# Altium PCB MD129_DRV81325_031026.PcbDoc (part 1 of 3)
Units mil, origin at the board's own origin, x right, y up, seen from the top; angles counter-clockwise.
Board outline 4300.91 x 4001.52 mil, 4 copper layers (Top Layer, GND, PWR, Bottom Layer), stack 92.668 mil thick; 211 components, 89 nets, 489 pads, 980 vias.
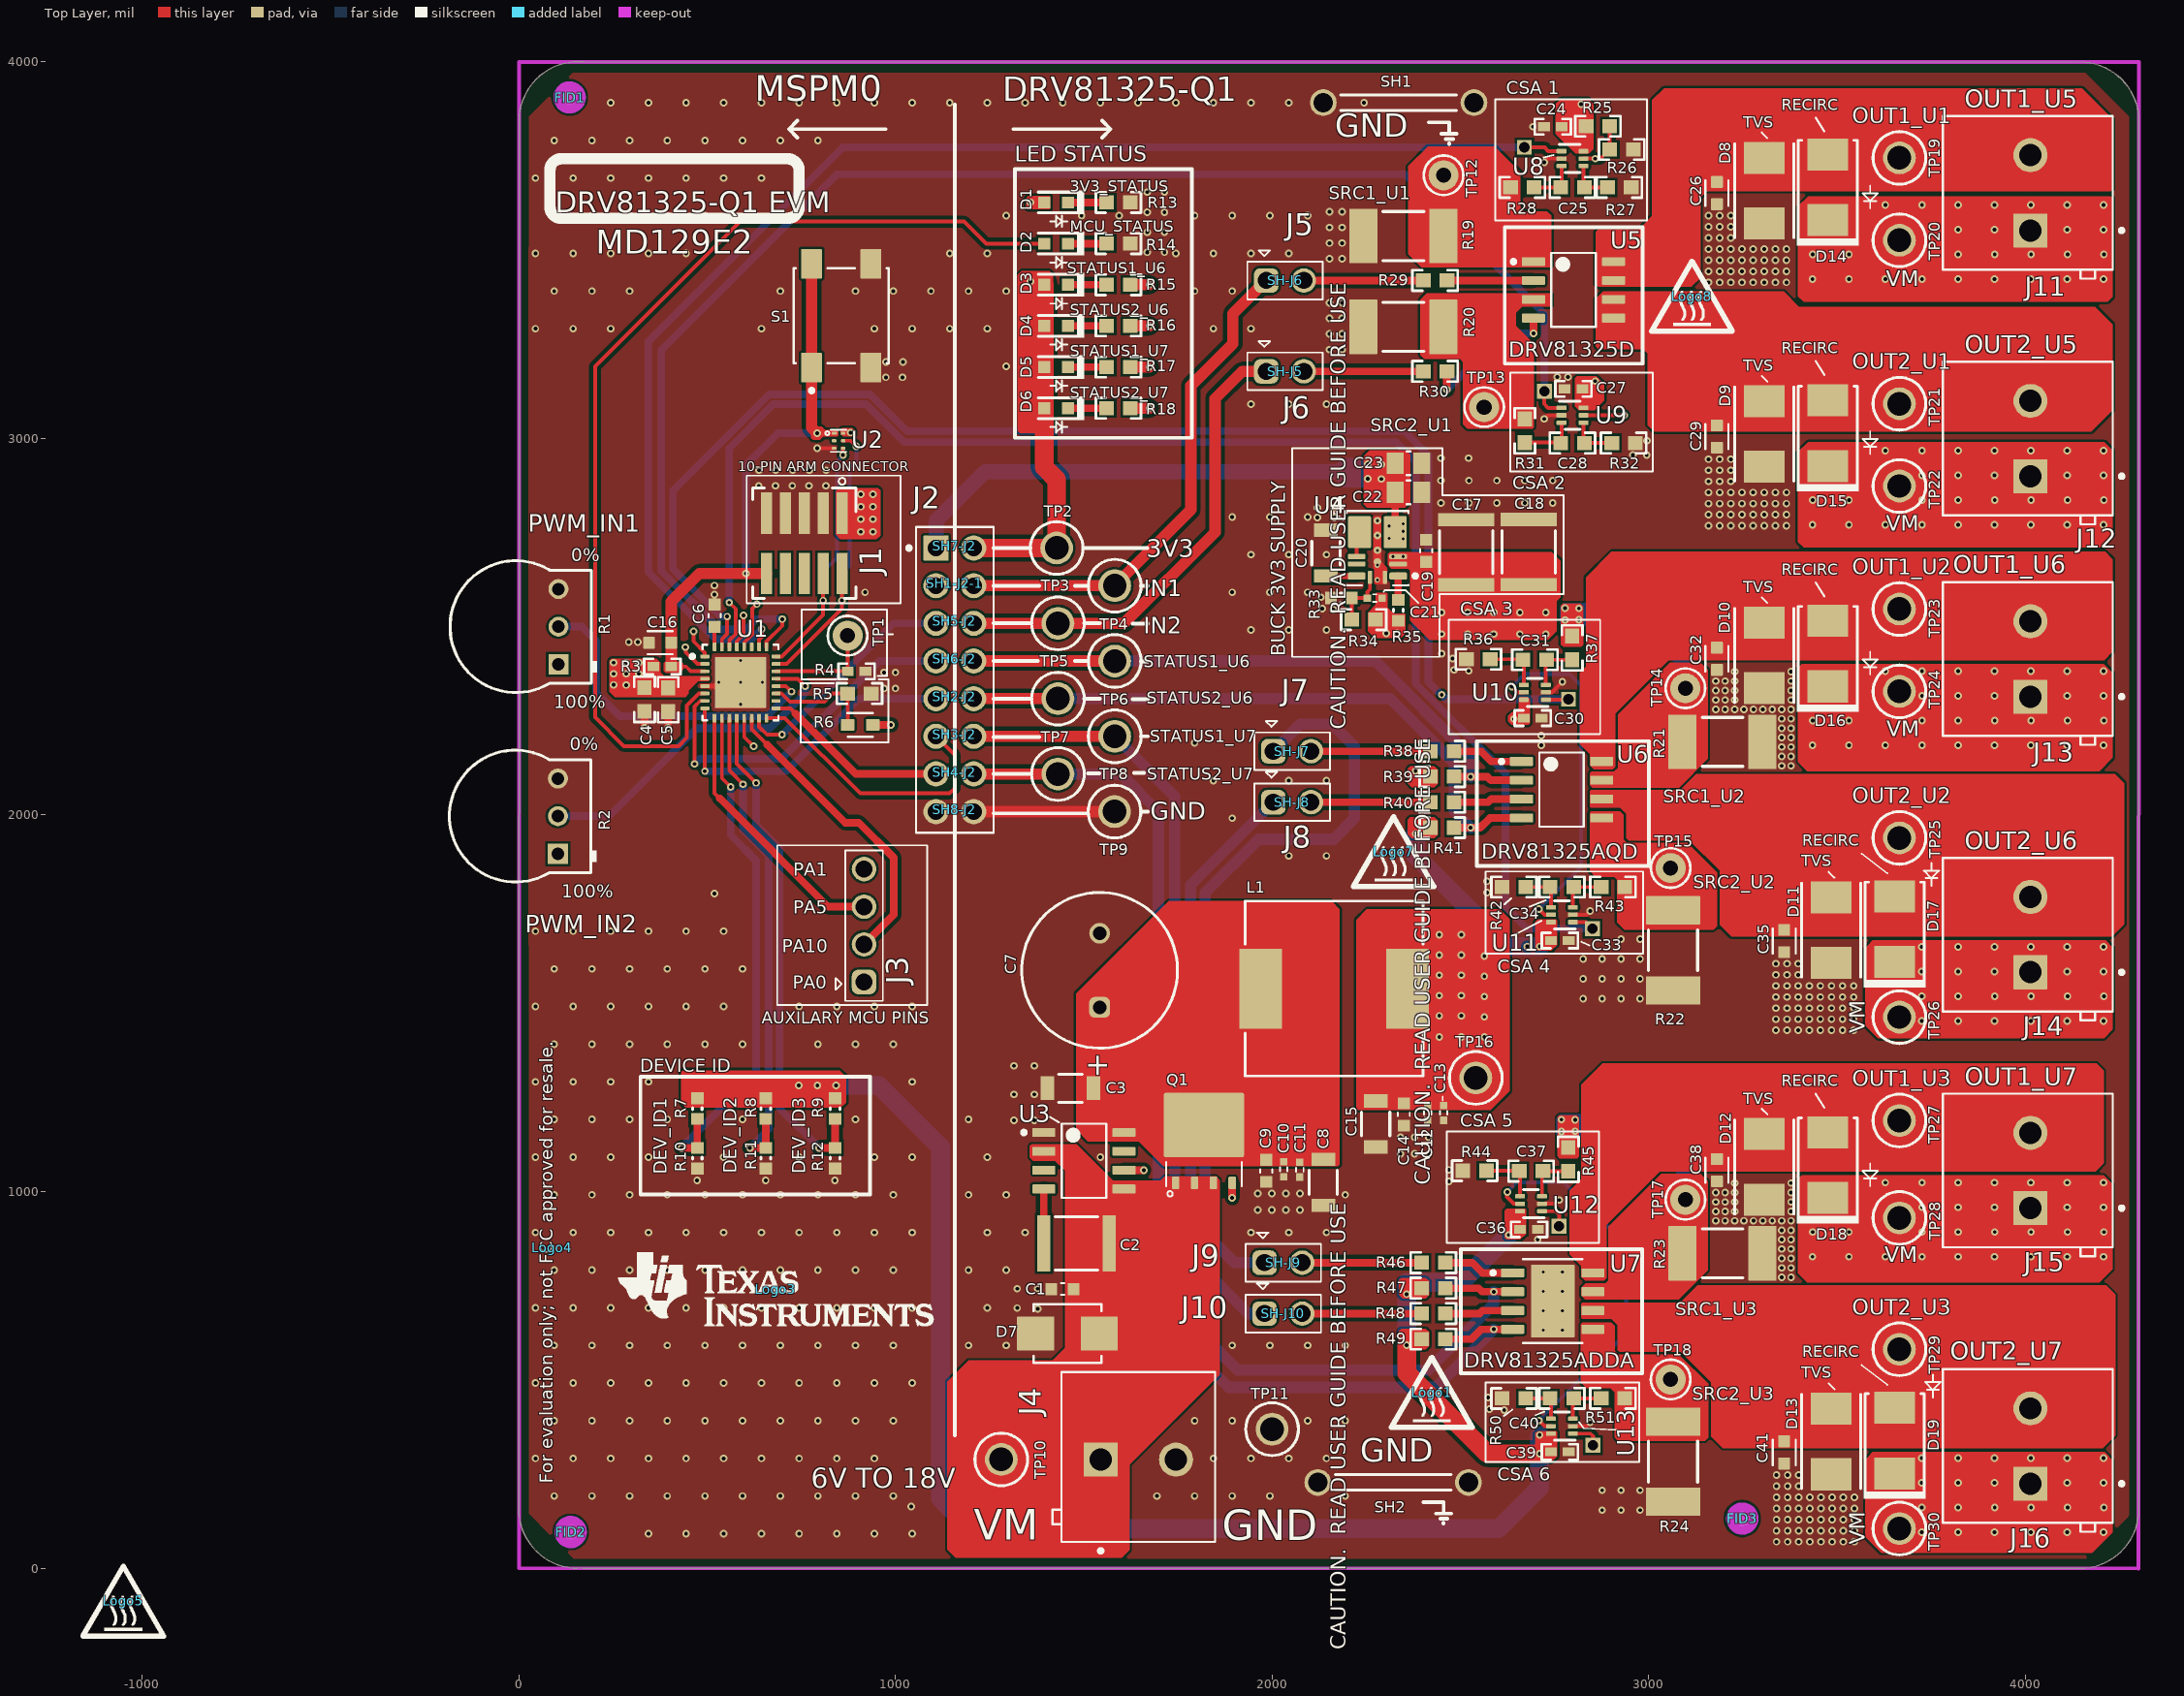
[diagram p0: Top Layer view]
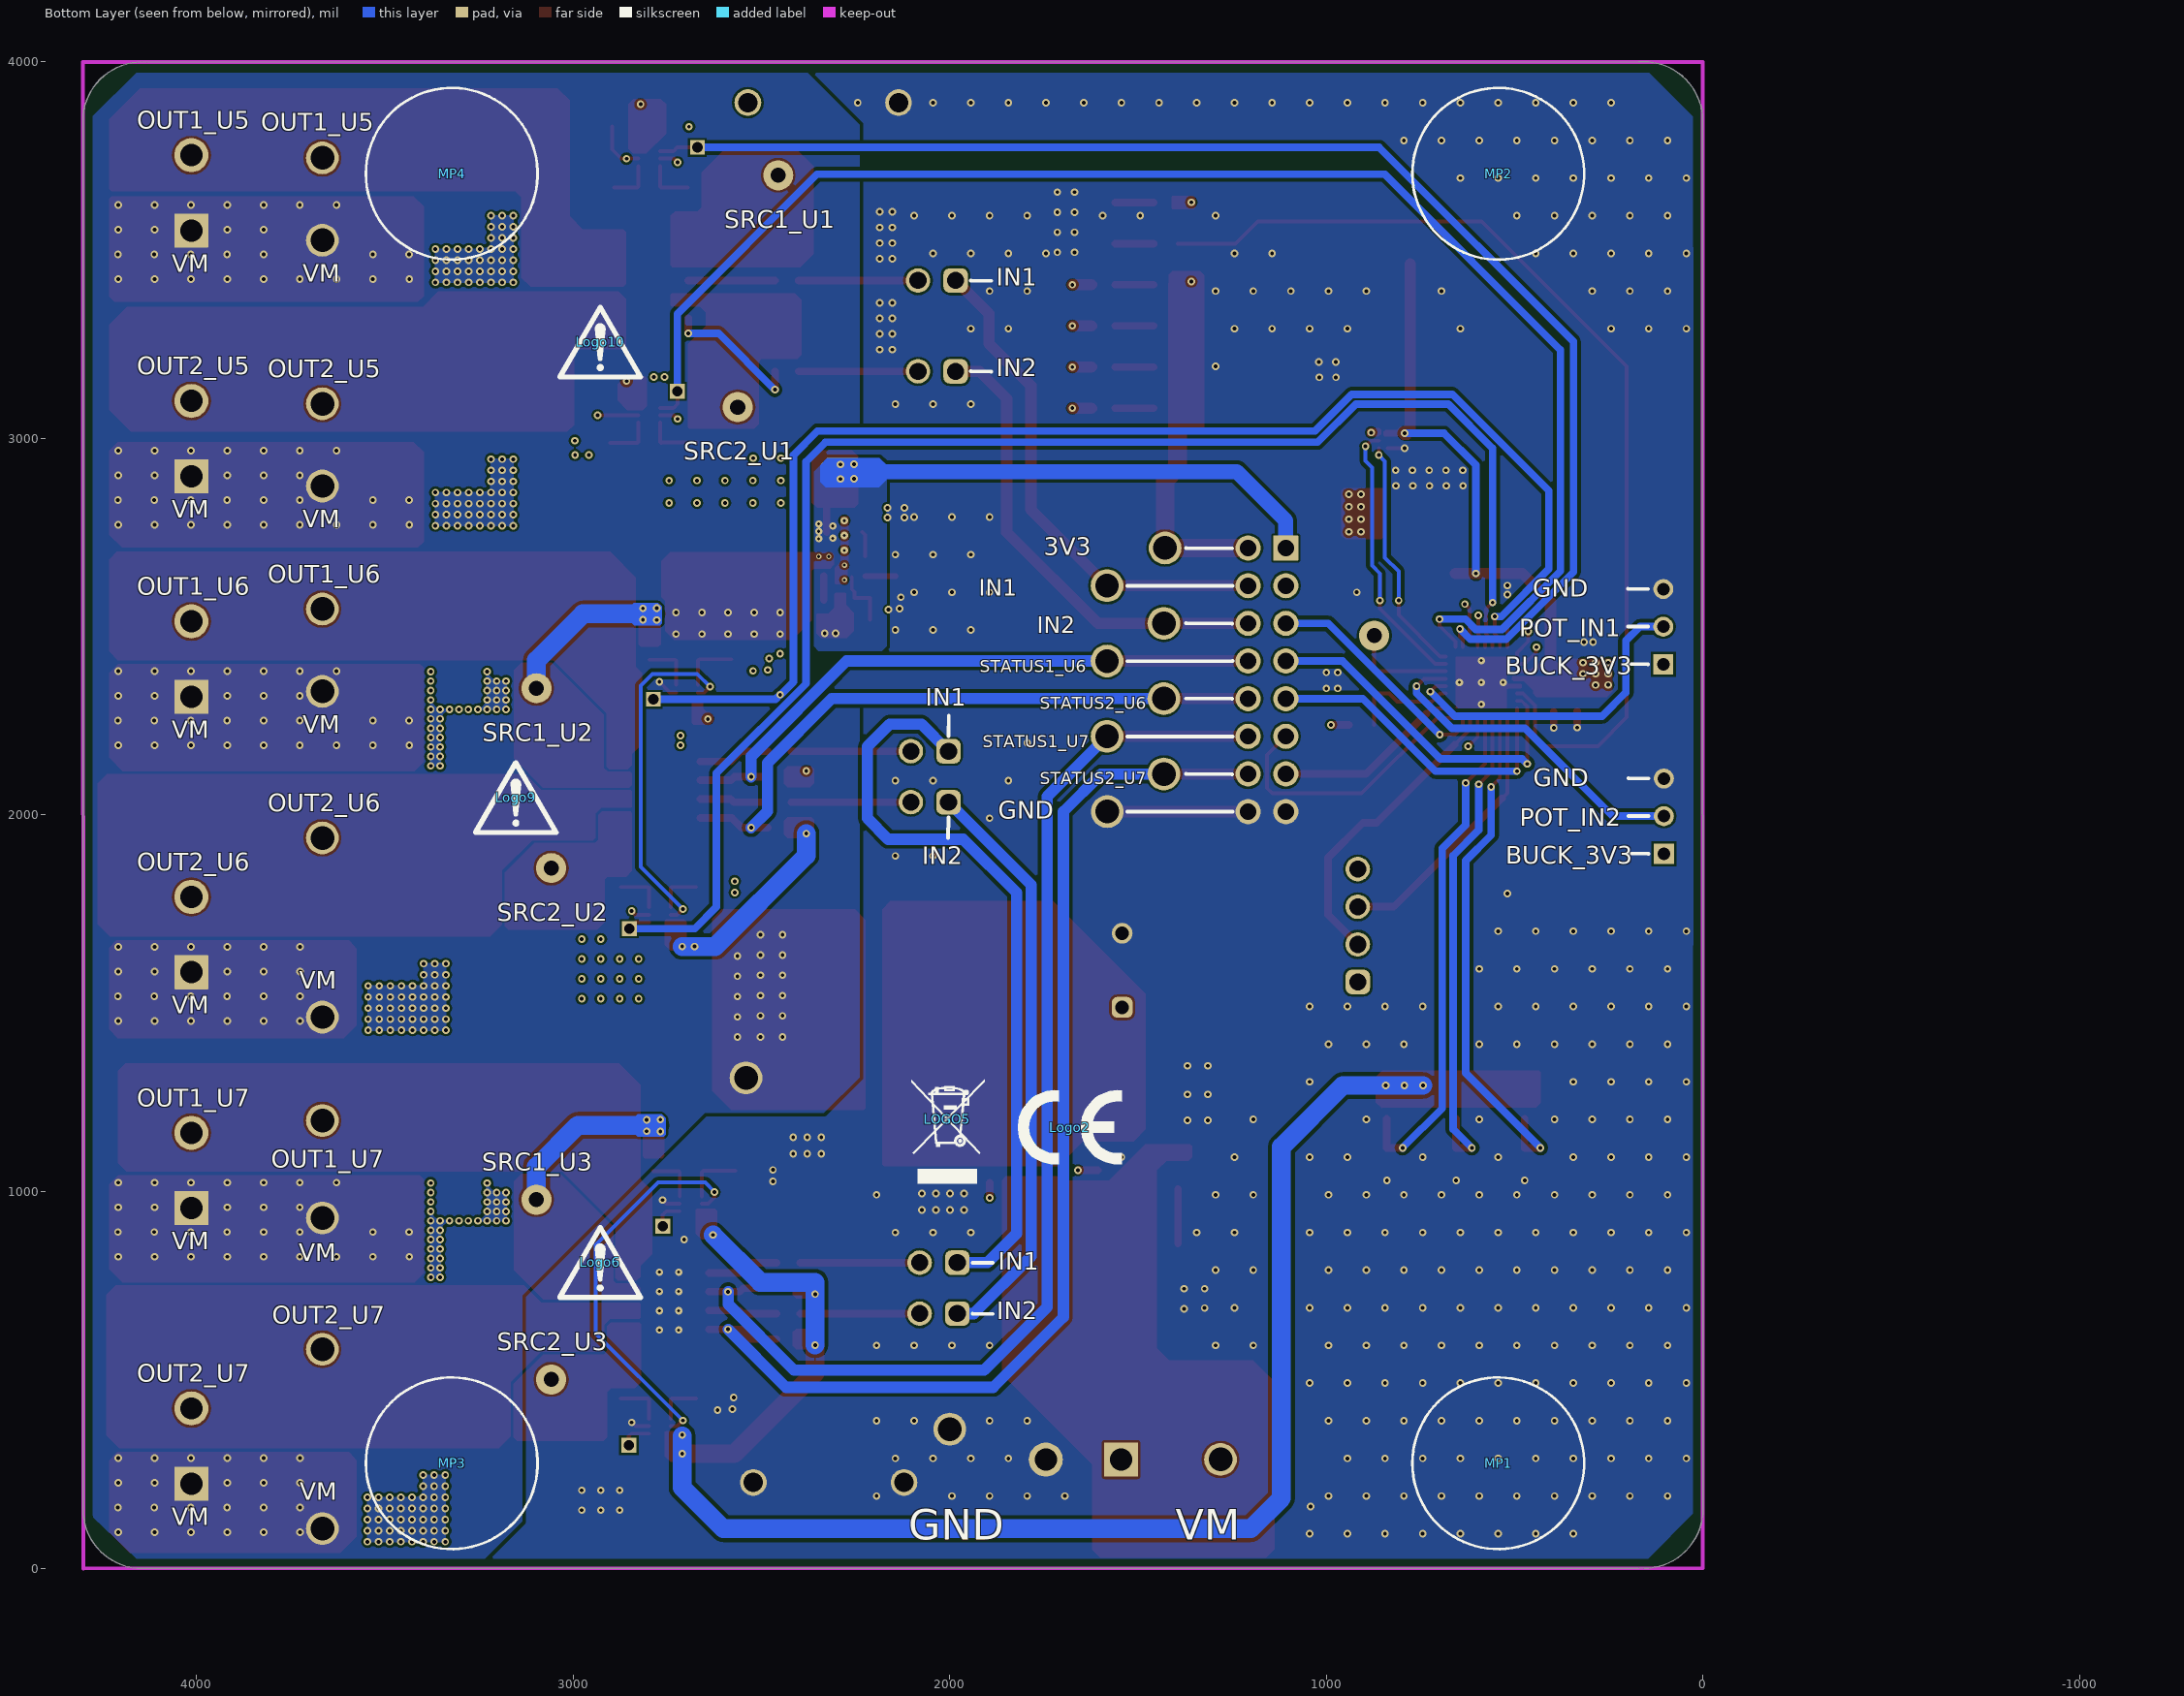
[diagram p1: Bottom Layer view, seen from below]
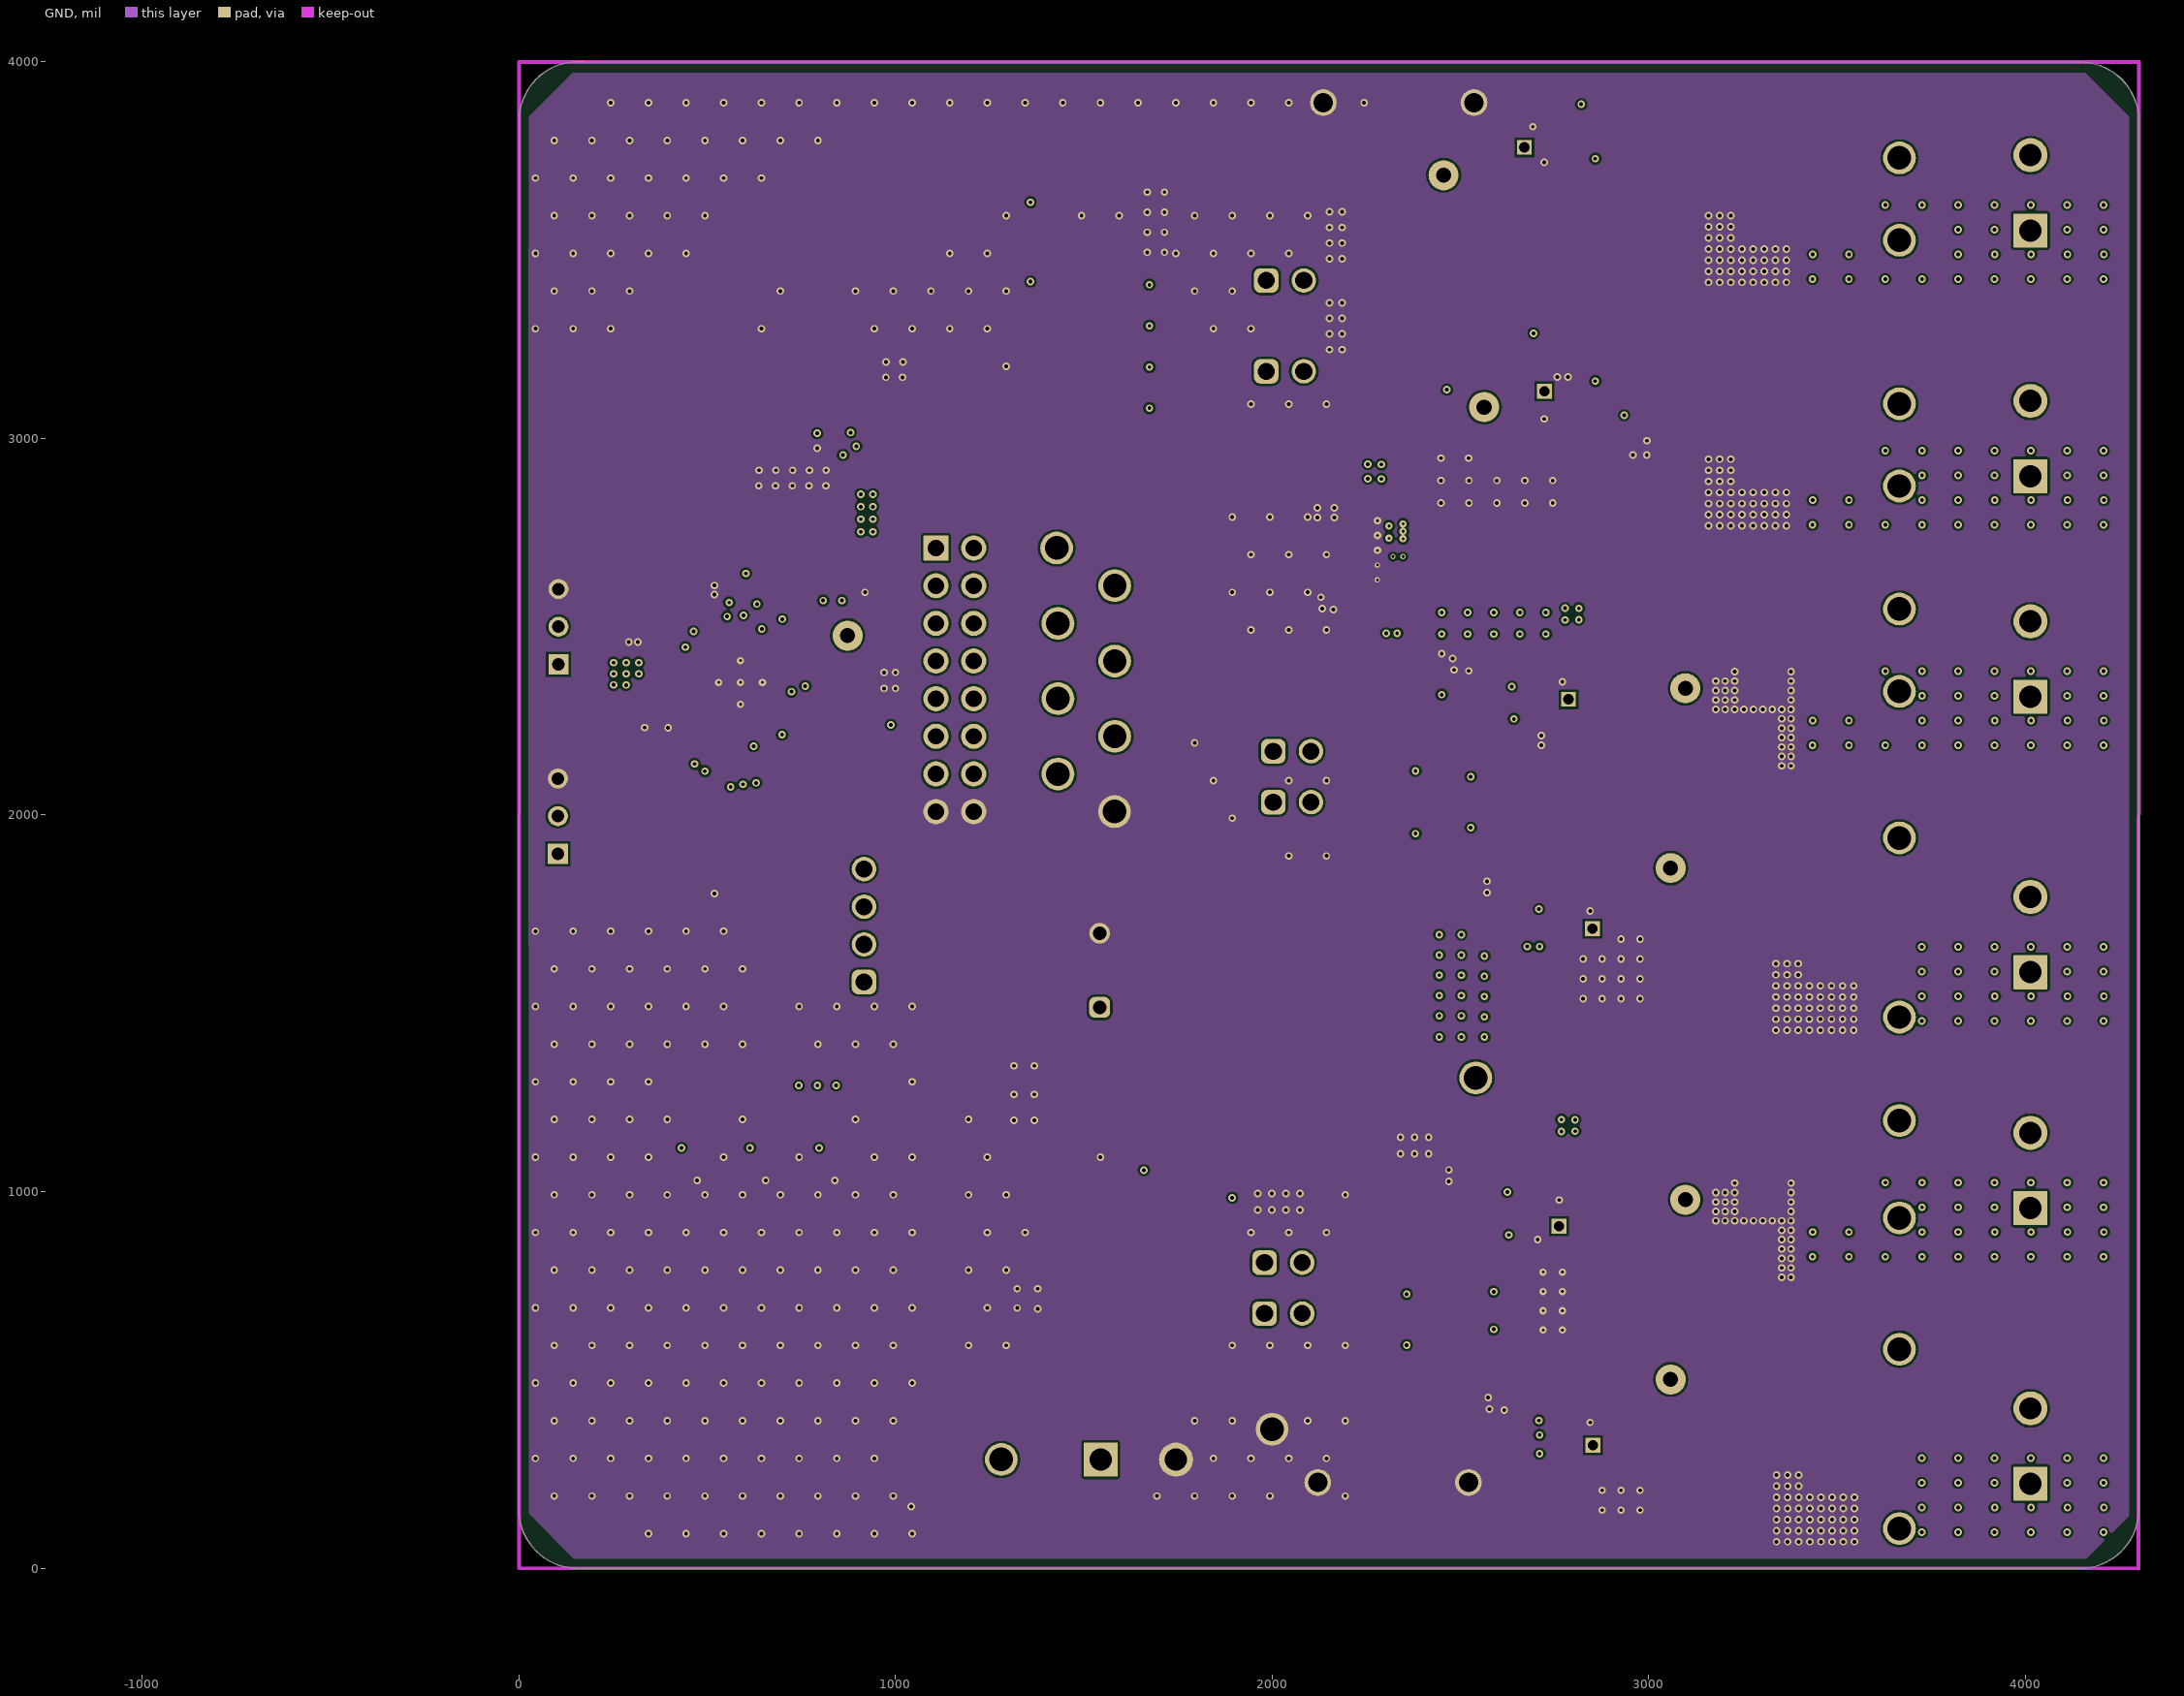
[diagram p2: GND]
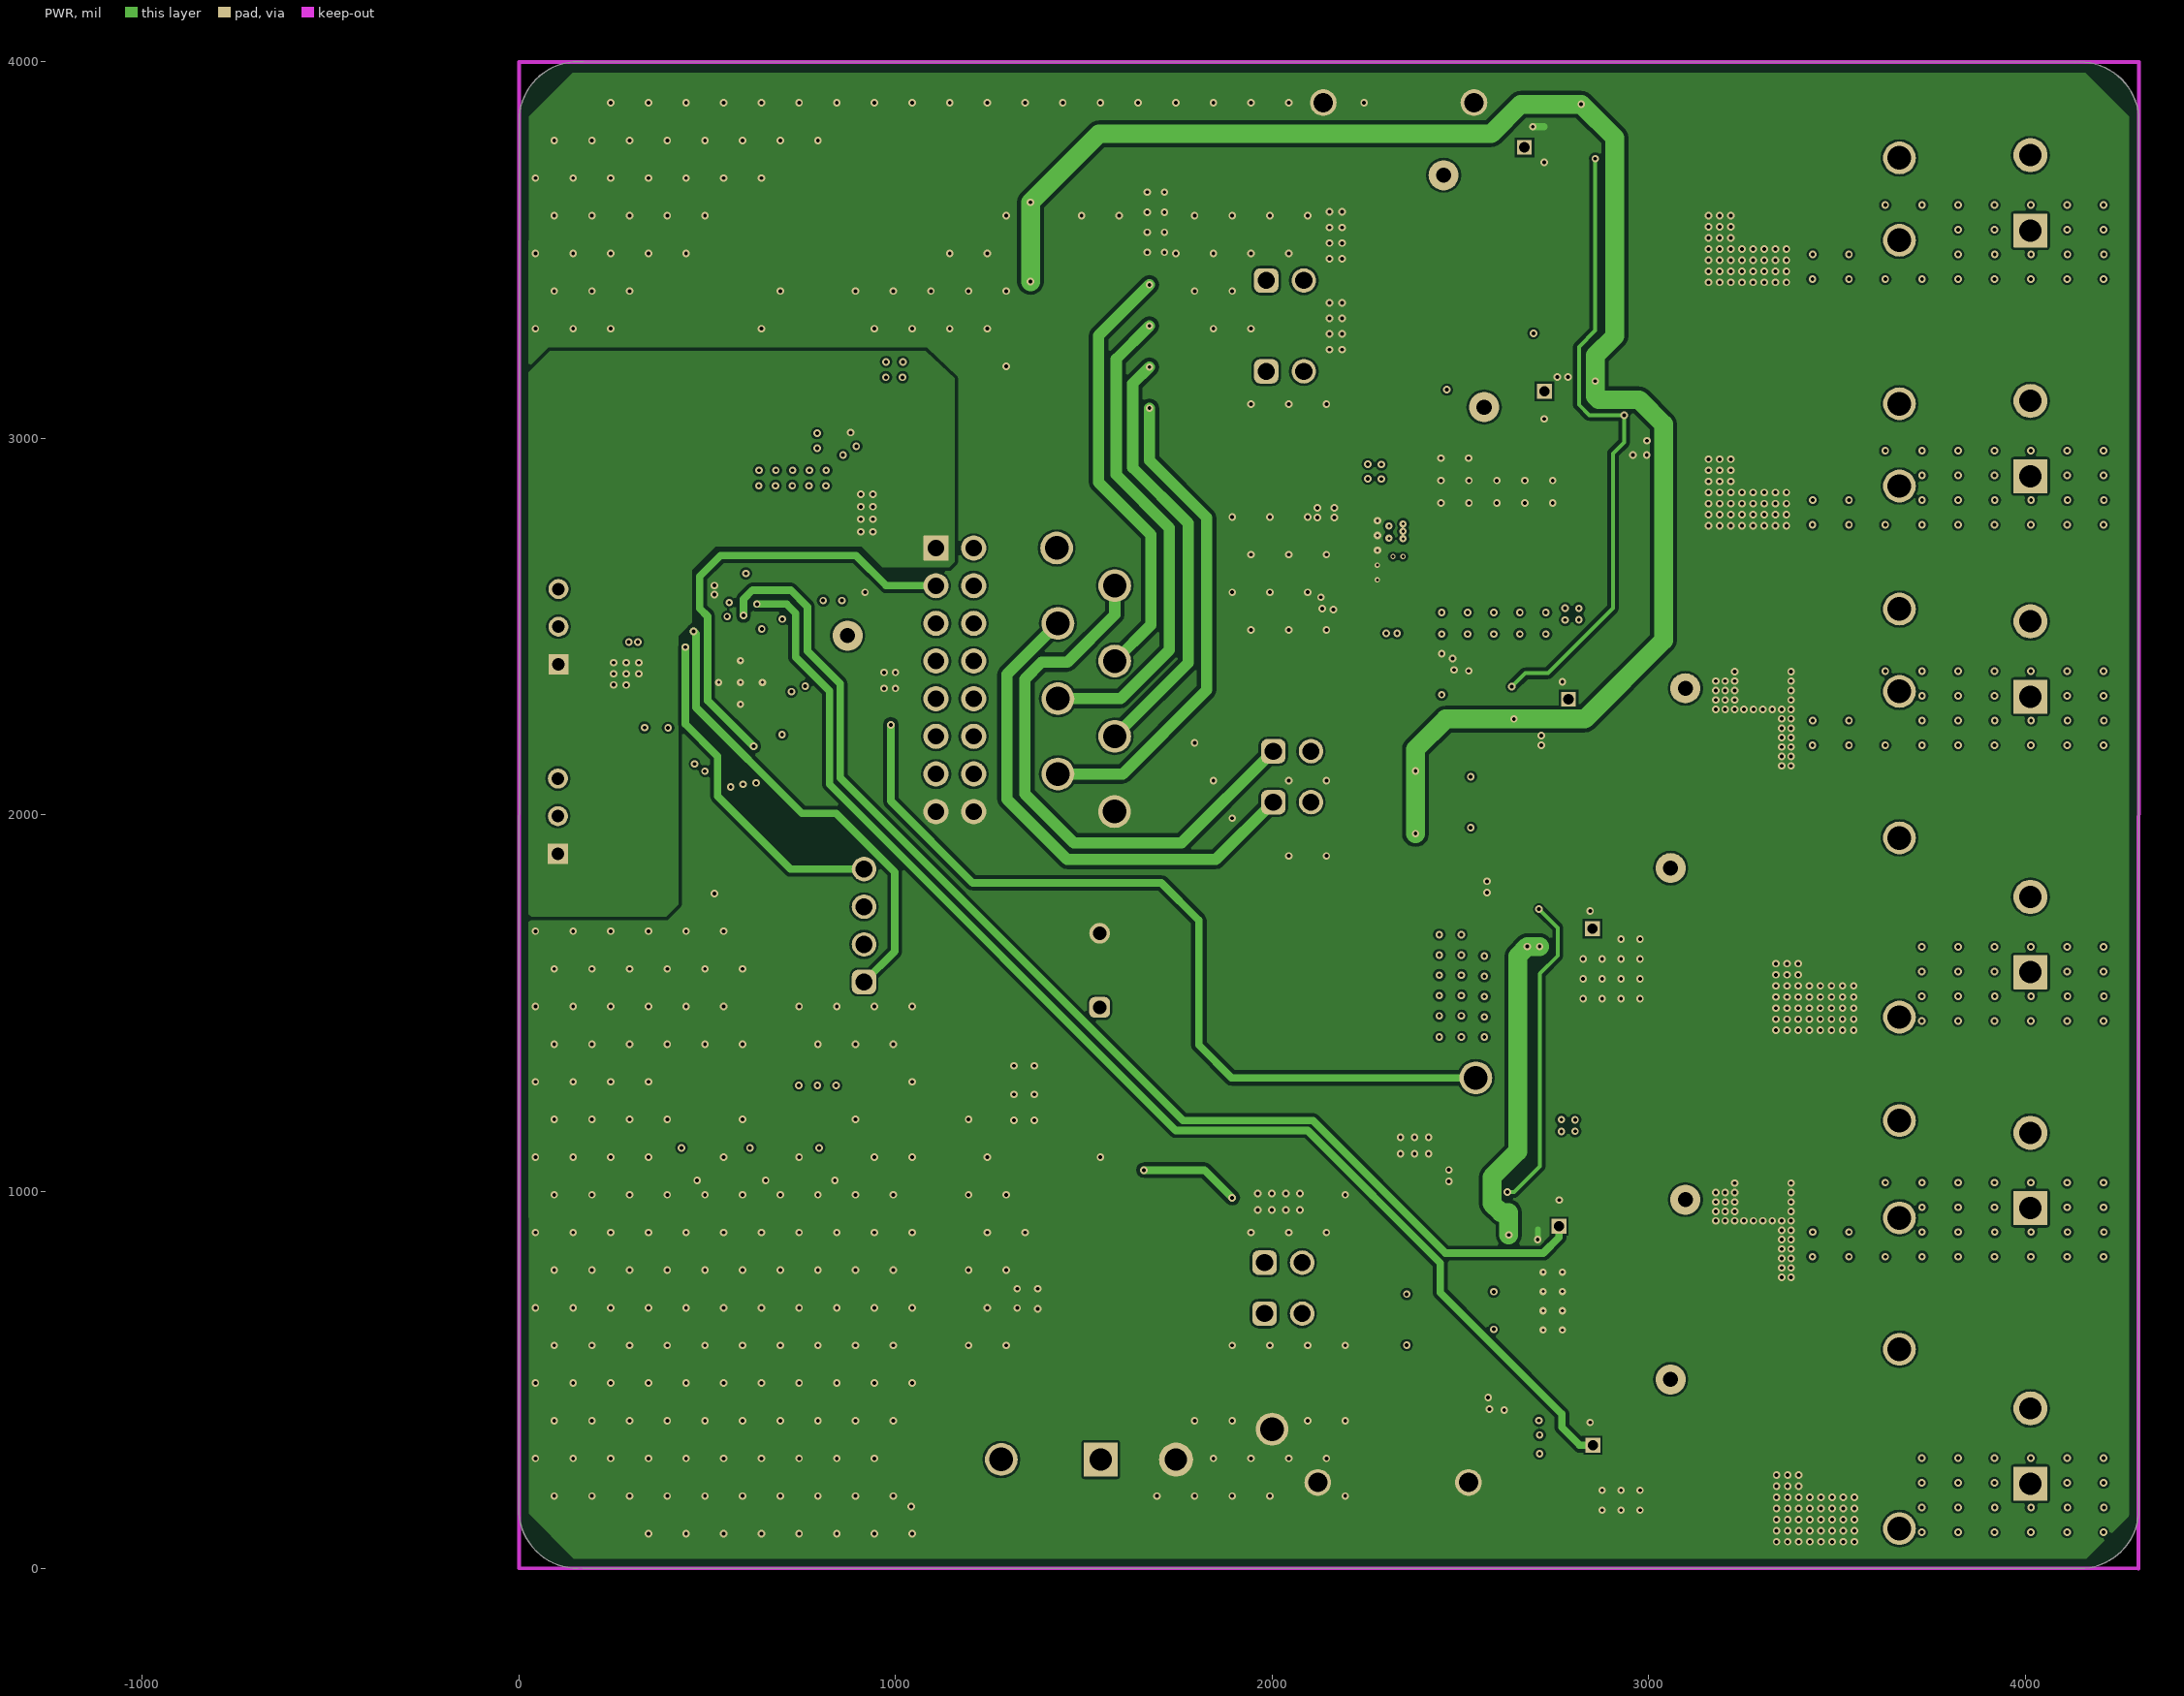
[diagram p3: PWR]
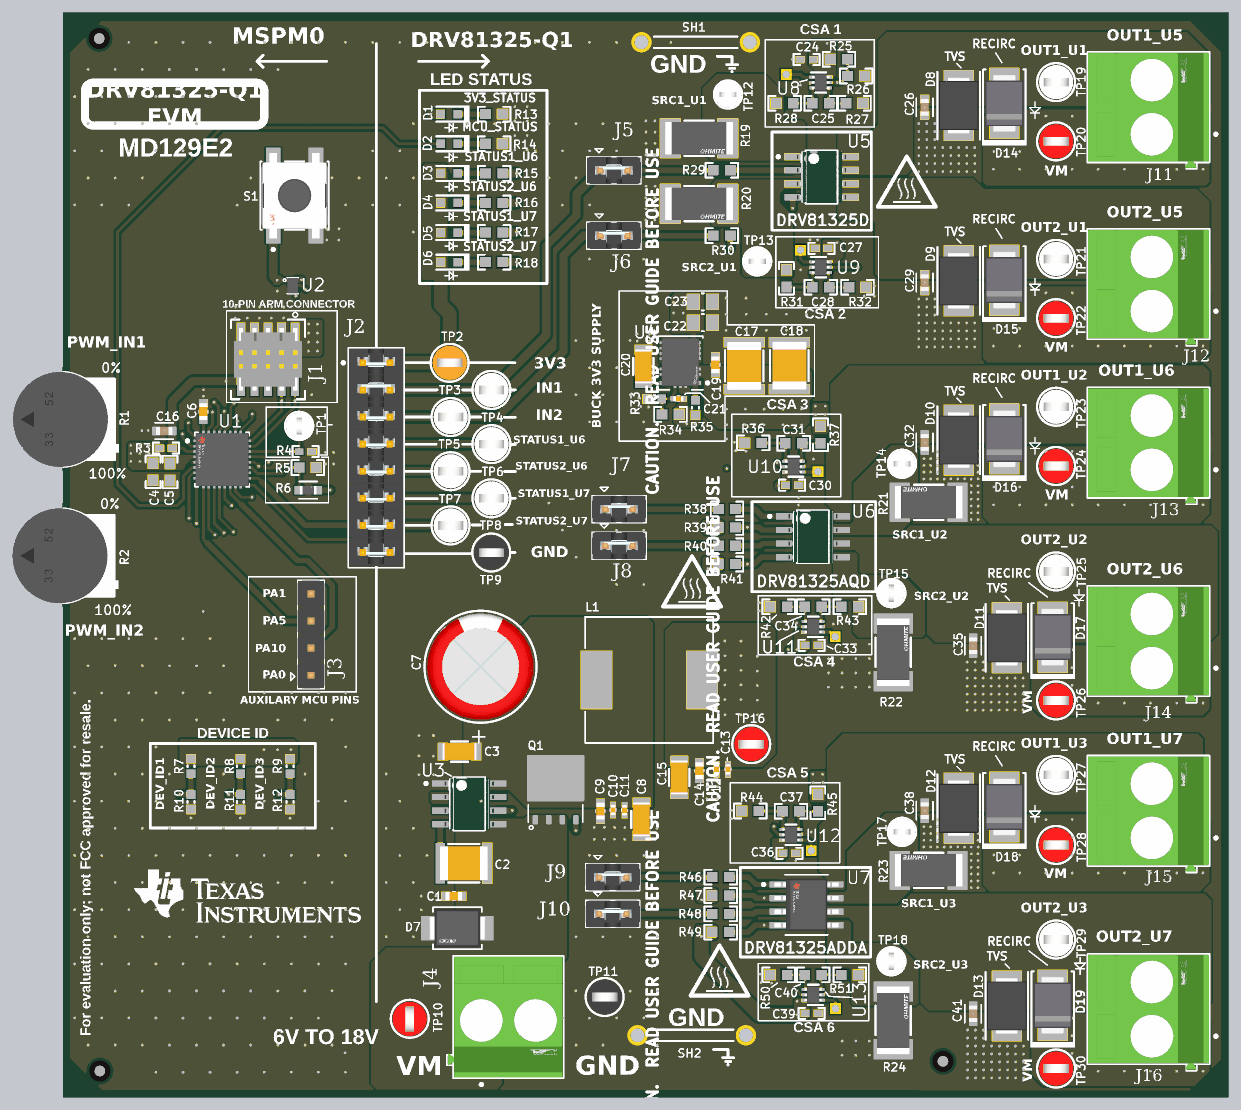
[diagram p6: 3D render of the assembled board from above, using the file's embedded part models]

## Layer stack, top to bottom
Top Solder: solder mask 0.4, Solder Resist, Dk 3.5
Top Layer: signal copper 2.756
Dielectric1: core 59.2, FR-4 High Tg, Dk 4.8
GND: signal copper 1.378
Dielectric 2: prepreg 12.6, FR-4 High Tg, Dk 4.8
PWR: signal copper 1.378
Dielectric 3: prepreg 12.6, FR-4 High Tg, Dk 4.8
Bottom Layer: signal copper 2.756
Bottom Solder: solder mask 0.4, Solder Resist, Dk 3.5

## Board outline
-0.03,143.05 ccw(c156.84,156.9) 170.69,0.03 169.89,-0.04 4157.62,-0.88 4156.95,-0.94 ccw(c4143.1,155.92) 4299.97,169.78 4300.04,168.98 4300.82,3856.71 4300.88,3856.04 ccw(c4144.01,3842.18) 4130.16,3999.05 4130.95,3999.12 171.55,3999.96 171.55,3999.97 ccw(c157.69,3843.1) 0.82,3856.95

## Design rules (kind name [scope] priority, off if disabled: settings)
AcuteAngle [All] p1: minimum=4.50000000000000E+0001 checktracksonly=FALSE
AssemblyTestPointUsage [All] p1: valid=2
BoardOutlineClearance BoardOutlineClearance_MountingHoles [OnCopper and InComponentClass('Mounting Holes')] p1: gap=15 ignorepadtopadclearanceinfootprint=FALSE
BoardOutlineClearance BoardOutlineClearance_Poly [OnCopper and IsPoly] p2: gap=25 ignorepadtopadclearanceinfootprint=FALSE
BoardOutlineClearance [OnCopper and Not InComponentClass('Logo') and not InComponentClass('FiducialMark') and not InRegion(1000,500,4000,800) and not InPoly] p3: gap=20 ignorepadtopadclearanceinfootprint=FALSE
Clearance [All] p1: gap=6 ignorepadtopadclearanceinfootprint=TRUE except(10: Track-Poly Poly-Poly)
Clearance Clearance_Keepouts [((IsTrack Or IsArc) And Not InPoly) And IsFree and IsKeepOut vs ((IsTrack Or IsArc) And Not InPoly) And IsFree and IsKeepOut] p2: gap=0 ignorepadtopadclearanceinfootprint=FALSE
Clearance Clearance_Poly [InPolygon] p3: gap=10 ignorepadtopadclearanceinfootprint=TRUE
Clearance Clearance_FiducialMark [IsKeepOut and InComponentClass('FiducialMark') vs IsPad and InComponentClass('FiducialMark')] p4: gap=0 ignorepadtopadclearanceinfootprint=TRUE
ComponentClearance ComponentClearance_Shunt [InComponentClass('Header') vs InComponentClass('Shunt')] p1: gap=0 collisioncheckmode=3 verticalgap=0 showdistances=FALSE
ComponentClearance ComponentClearance_PI_FILTER_R75 [InComponent('R75') vs InComponent('L1')] p2: gap=0 collisioncheckmode=3 verticalgap=0 showdistances=FALSE
ComponentClearance ComponentClearance_PI_FILTER_R66 [InComponent('R66') vs InComponent('L1')] p3: gap=0 collisioncheckmode=3 verticalgap=0 showdistances=FALSE
ComponentClearance ComponentClearance_CANL_Choke [InComponent('L2') vs InComponent('R71')] p4: gap=0 collisioncheckmode=3 verticalgap=0 showdistances=FALSE
ComponentClearance ComponentClearance_CANH_Choke [InComponent('L2') vs InComponent('R68')] p5: gap=0 collisioncheckmode=3 verticalgap=0 showdistances=FALSE
ComponentClearance ComponentClearance_MountingHoles_FiducialMarks [InComponentClass('Mounting Holes') vs InComponentClass('FiducialMark')] p6: gap=50 collisioncheckmode=3 verticalgap=10 showdistances=FALSE
ComponentClearance ComponentClearance_Logo [InComponentClass('Logo')] p7: gap=30 collisioncheckmode=3 verticalgap=10 showdistances=FALSE
ComponentClearance ComponentClearance_ScrewToNut [(HasFootprint('NY PMS 440 0025 PH')) vs (HasFootprint('Keystone_1902C'))] p8: gap=5 collisioncheckmode=3 verticalgap=10 showdistances=FALSE
ComponentClearance ComponentClearance_MountingHoles [InComponentClass('Mounting Holes')] p9: gap=100 collisioncheckmode=3 verticalgap=100000 showdistances=FALSE
ComponentClearance ComponentClearance_SmallPassives [HasFootprint('0201*') or HasFootprint('0402*') or HasFootprint('0508') or HasFootprint('0603*') or HasFootprint('0612') or HasFootprint('0805*') or HasFootprint('0815*') or HasFootprint('0830*') or HasFootprint('1206*') or HasFootprint('1210*') or HasFootprint('1808*') or HasFootprint('1812*') or HasFootprint('1825*') or HasFootprint('2010*') or HasFootprint('2220*') or HasFootprint('2225*') or HasFootprint('2512*') or HasFootprint('2728*') or HasFootprint('3518*') vs HasFootprint('0201*') or HasFootprint('0402*') or HasFootprint('0508') or HasFootprint('0603*') or HasFootprint('0612') or HasFootprint('0805*') or HasFootprint('0815*') or HasFootprint('0830*') or HasFootprint('1206*') or HasFootprint('1210*') or HasFootprint('1808*') or HasFootprint('1812*') or HasFootprint('1825*') or HasFootprint('2010*') or HasFootprint('2220*') or HasFootprint('2225*') or HasFootprint('2512*') or HasFootprint('2728*') or HasFootprint('3518*')] p10: gap=14.96 collisioncheckmode=3 verticalgap=10 showdistances=FALSE
ComponentClearance ComponentClearance_THtoSMT [IsThruComponent vs IsSMTComponent] p11: gap=30 collisioncheckmode=3 verticalgap=30 showdistances=FALSE
ComponentClearance ComponentClearance_THtoTH [IsThruComponent vs IsThruComponent] p12: gap=20 collisioncheckmode=3 verticalgap=30 showdistances=FALSE
ComponentClearance [All] p13: gap=20 collisioncheckmode=3 verticalgap=10 showdistances=FALSE
DiffPairsRouting [All] p1: maxlimit=100 minlimit=10 mostfreqgap=10 toplayer_minwidth=6 toplayer_maxwidth=15 toplayer_prefwidth=10 midlayer1_minwidth=6 midlayer1_maxwidth=15 midlayer1_prefwidth=10 midlayer2_minwidth=6 midlayer2_maxwidth=15 midlayer2_prefwidth=10 bottomlayer_minwidth=6 bottomlayer_maxwidth=15 bottomlayer_prefwidth=10 maxuncoupledlength=1000
FabricationTestPointUsage TestPointUsage [All] p1: valid=2 allowmultiple=FALSE
FabricationTestpoint Testpoint [All] p1: side=3 testpointundercomponent=TRUE minsize=40 maxsize=100 preferedsize=60 minholesize=0 maxholesize=40 preferedholesize=32 testpointgrid=1 allowsidetop=TRUE allowsidebottom=TRUE usegrid=TRUE gridtolerance=0.01
FanoutControl Fanout_LCC [IsLCC] p1: bgadir=Out bgaviamode=Centered fanoutstyle=Auto fanoutdirection=Alternating viagrid=1 // Fanout_LCC (Default Rule)
FanoutControl Fanout_BGA [IsBGA] p2: bgadir=Out bgaviamode=Centered fanoutstyle=Auto fanoutdirection=Alternating viagrid=1 // Fanout_BGA (Default Rule)
FanoutControl Fanout_Default [All] p4: bgadir=Out bgaviamode=Centered fanoutstyle=Auto fanoutdirection=Alternating viagrid=1 // Fanout_Default (Default Rule)
FanoutControl Fanout_Small [(CompPinCount < 5)] p5: bgadir=Out bgaviamode=Centered fanoutstyle=Auto fanoutdirection=OutThenIn viagrid=1 // Fanout_Small (Default Rule)
HoleSize [All] p1: absolutevalues=TRUE maxlimit=251 minlimit=7.87 maxpercent=80.000 minpercent=20.000
MinimumAnnularRing MinimumAnnularRing_ThermalPadVias [IsVia and InAnyComponent] p1: minimumring=5.91
MinimumAnnularRing [All] p2: minimumring=5.91
MinimumSolderMaskSliver MinimumSolderMaskSliver_Logo [InComponentClass('Logo') vs InComponentClass('Logo')] p1: minsoldermaskwidth=0.7
MinimumSolderMaskSliver [All] p2: minsoldermaskwidth=3.94
PlaneClearance [All] p1: clearance=10
PlaneConnect [All] p1: planeconnectstyle=Direct reliefexpansion=10 reliefentries=4 reliefconductorwidth=10 reliefairgap=10
PolygonConnect [All] p1: connectstyle=Direct reliefconductorwidth=10 reliefentries=4 polygonreliefangle="90 Angle" airgapwidth=10
RoutingVias ThermalPadVias [IsVia and InAnyComponent] p1: holewidth=7.87 width=19.68 viastyle="Through Hole" minholewidth=7.87 minwidth=19.68 maxholewidth=12.99 maxwidth=23.62
RoutingVias [All] p2: holewidth=16 width=34 viastyle="Through Hole" minholewidth=7.87 minwidth=19.68 maxholewidth=236.22 maxwidth=236.22
SilkToBoardRegionClearance [Not ((IsComment or IsDesignator) And (Hide <> 'False')) and not InRegion(1000,500,4000,800)] p1:
SilkToSilkClearance SilkToSilkClearance_Pb-FreeLogo [(HasFootprint('Pb-Free_Overlay_Medium') OR HasFootprint('Pb-Free_Overlay_Small')) vs (HasFootprint('Pb-Free_Overlay_Medium') OR HasFootprint('Pb-Free_Overlay_Small'))] p1: silktosilkclearance=0
SilkToSilkClearance [All] p2: silktosilkclearance=3.94
SilkToSolderMaskClearance SilkToComponentPadClearance [(IsPad or IsFill or IsRegion) and InAnycomponent] p1: minsilkscreentomaskgap=5 clearancetoexposedcopper=TRUE
SilkToSolderMaskClearance "Silk to Solder Mask Opening" [All] p2: minsilkscreentomaskgap=3.94 clearancetoexposedcopper=FALSE
SolderMaskExpansion [All] p1: expansion=1.97 istentingtop=FALSE
UnRoutedNet [All] p1: checkbadconnections=TRUE
Width [All] p1: maxlimit=100 minlimit=6 preferedwidth=10 checkconnectedcopper=TRUE
13 further rules are at their usual default settings.

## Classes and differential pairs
component class DRV81325-QAD_IC: C30 C31 C32 C33 C34 C35 D10 D11 D16 D17 J7 J8 J13 J14 R21 R22 R36 R37 R38 R39 R40 R41 R42 R43 SH-J7 SH-J8 TP14 TP15 TP23 TP24 TP25 TP26 U6 U10 U11
component class DRV81325-Q1_HW: !PCB1 FID1 FID2 FID3 Logo2 Logo3 Logo4 LOGO5 Logo6 MP1 MP2 MP3 MP4 ZZ1 ZZ2 ZZ3 ZZ4
component class DRV81325-QADDA_IC: 15 C36 C37 C38 C39 C40 C41 D12 D13 D18 D19 J9 J10 J15 J16 L? R23 R24 R44 R45 R46 R47 R48 R49 R50 R51 SH-J9 SH-J10 TP17 TP18 TP27 TP28 TP29 TP30 U7 U12 U13
component class DRV81325-QD_IC: C24 C25 C26 C27 C28 C29 D8 D9 D14 D15 J5 J6 J11 J12 R19 R20 R25 R26 R27 R28 R29 R30 R31 R32 SH1 SH2 SH-J5 SH-J6 TP12 TP13 TP19 TP20 TP21 TP22 U5 U8 U9
component class DRV81325-Q1_MCU_Supply: 20 C1 C2 C3 C4 C5 C6 C7 C8 C9 C10 C11 C12 C13 C14 C15 C16 C17 C18 C19 C20 C21 C22 C23 D1 D2 D3 D4 D5 D6 D7 J1 J2 J3 J4 L1 Q1 R1 R2 R3 R4 R5 R6 R7 R8 R9 R10 R11 R12 R13 R14 R15 R16 R17 R18 R33 R34 R35 S1 SH1-J2-1 SH2-J2 SH3-J2 SH4-J2 SH5-J2 SH6-J2 SH7-J2 SH8-J2 TP1 TP2 TP3 TP4 TP5 TP6 TP7 TP8 TP9 TP10 TP11 TP16 U1 U2 U3 U4

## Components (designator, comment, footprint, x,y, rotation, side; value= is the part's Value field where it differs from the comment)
C1 "885012206091" WCAP-CSGP_0603_L1.6W0.8H0.8_REFLOW 1443.3,740.78 r0 top
C2 "885012210032" WCAP-CSGP_1812_L4.5W3.2H2.5 1480.39,862.45 r0 top
C3 "885012208093" WCAP-CSGP_1206_L3.2W1.6H1.6 1464.28,1274.3 r0 top
C4 "GRM188R61E106KA73D" 0603 333.52,2306.87 r270 top value=10uF
C5 "885012206095" 0603 396.02,2306.17 r270 top value=0.1uF
C6 "885012206075R" WCAP-CSGP_0603_L1.6W0.8H0.8_REFLOW 519.44,2529.22 r270 top value=470nF
C7 "860040875004" WCAP-ATUL_D10H20 1541.82,1587.48 r270 top value=82µF
C8 "885012208093" WCAP-CSGP_1206_L3.2W1.6H1.6 2135.5,1024.33 r90 top value=1µF
C9 "885012206095" WCAP-CSGP_0603_L1.6W0.8H0.8_REFLOW 1984.4,1054.82 r90 top value=100nF
C10 "885012205067" WCAP-CSGP_0402_L1W0.5H0.5 2030.81,1058.96 r90 top value=10nF
C11 "885012205061" WCAP-CSGP_0402_L1W0.5H0.5 2073.33,1058.01 r90 top value=1nF
C12 "885012205061" WCAP-CSGP_0402_L1W0.5H0.5 2412.72,1208.77 r90 top value=1nF
C13 "885012205067" WCAP-CSGP_0402_L1W0.5H0.5 2455,1208.77 r90 top value=10nF
C14 "885012206095" WCAP-CSGP_0603_L1.6W0.8H0.8_REFLOW 2349.59,1204.47 r90 top value=100nF
C15 "885012208093" WCAP-CSGP_1206_L3.2W1.6H1.6 2274.95,1179.37 r90 top value=1µF
C16 "885012206065" FP-885012206065_0603-MFG 374.88,2457.28 r180 top value=10nF
C17 "885012210032" WCAP-CSGP_1812_L4.5W3.2H2.5 2514.71,2697.57 r270 top value=2.2µF
C18 "885012210032" WCAP-CSGP_1812_L4.5W3.2H2.5 2681.4,2698.42 r270 top value=2.2µF
C19 "885012206095" WCAP-CSGP_0603_L1.6W0.8H0.8_REFLOW 2408.52,2701.42 r270 top value=100nF
C20 "885012208093" WCAP-CSGP_1206_L3.2W1.6H1.6 2142.5,2695.62 r270 top value=1µF
C21 "885012005029" WCAP-CSGP_0402_L1W0.5H0.5 2272.13,2576.02 r0 top value=47pF
C22 "885012107014" 0805_150 2362.01,2857.12 r0 top value=10uF
C23 "885012107014" 0805_150 2362.01,2933.66 r0 top value=10uF
C24 "885012105001" 0402 2745.11,3827.86 r0 top value=0.1uF
C25 "885012206046" 0603 2797.21,3666.39 r0 top value=0.1uF
C26 "885012206091" FP-885012206091_0603-MFG#1 3180.64,3651.6 r90 top value=22nF
C27 "885012105001" 0402 2799.93,3131.49 r0 top value=0.1uF
C28 "885012206046" 0603 2797.21,2987.75 r0 top value=0.1uF
C29 "885012206091" FP-885012206091_0603-MFG#1 3180.64,3005.03 r90 top value=22nF
C30 "885012105001" 0402 2691.7,2257.32 r180 top value=0.1uF
C31 "885012206046" 0603 2697.21,2412.23 r180 top value=0.1uF
C32 "885012206091" FP-885012206091_0603-MFG#2 3180.64,2414.92 r90 top value=22nF
C33 "885012105001" 0402 2763.61,1666.65 r180 top value=0.1uF
C34 "885012206046" 0603 2769.12,1808.74 r180 top value=0.1uF
C35 "885012206091" FP-885012206091_0603-MFG#2 3359.27,1665.3 r90 top value=22nF
C36 "885012105001" 0402 2681.7,899.15 r180 top value=0.1uF
C37 "885012206046" 0603 2687.21,1054.06 r180 top value=0.1uF
C38 "885012206091" FP-885012206091_0603-MFG#2 3180.64,1056.75 r90 top value=22nF
C39 "885012105001" 0402 2763.61,308.48 r180 top value=0.1uF
C40 "885012206046" 0603 2769.12,450.58 r180 top value=0.1uF
C41 "885012206091" FP-885012206091_0603-MFG#2 3359.27,307.14 r90 top value=22nF
D1 "150060VS75000" WL-SMCW_GREEN 1426.18,3626.44 r180 top value=Green
D2 "150060VS75000" WL-SMCW_GREEN 1426.18,3517.21 r180 top value=Green
D3 "150060RS75000" WL-SMCW_RED 1426.18,3407.98 r180 top value=Red
D4 "150060RS75000" WL-SMCW_RED 1426.18,3298.75 r180 top value=Red
D5 "150060RS75000" WL-SMCW_RED 1426.18,3189.52 r180 top value=Red
D6 "150060RS75000" WL-SMCW_RED 1426.18,3080.28 r180 top value=Red
D7 "SMBJ36CA-13-F" FP-SMBJ36CA-13-F_SMB-MFG 1456.32,622.85 r180 top
D8 "SMBJ33CA-13-F" SMB-Bi 3306.09,3658 r90 top value=33V
D9 "SMBJ33CA-13-F" SMB-Bi 3306.09,3011.43 r90 top value=33V
D10 "SMBJ33CA-13-F" SMB-Bi 3306.09,2423.58 r90 top value=33V
D11 "SMBJ33CA-13-F" SMB-Bi 3483.98,1694.18 r90 top value=33V
D12 "SMBJ33CA-13-F" SMB-Bi 3306.09,1065.41 r90 top value=33V
D13 "SMBJ33CA-13-F" SMB-Bi 3483.98,336.02 r90 top value=33V
D14 "SS24T3G" SMB 3474.83,3666.43 r90 top value=40V
D15 "SS24T3G" SMB 3474.83,3013.85 r90 top value=40V
D16 "SS24T3G" SMB 3474.83,2428.43 r90 top value=40V
D17 "SS24T3G" SMB 3652.71,1696.6 r90 top value=40V
D18 "SS24T3G" SMB 3474.83,1070.27 r90 top value=40V
D19 "SS24T3G" SMB 3652.71,338.44 r90 top value=40V
FID1 "Fiducial" Fiducial10-20 134.63,3905.43 r0 top
FID2 "Fiducial" Fiducial10-20 137.35,95.78 r0 top
FID3 "Fiducial" Fiducial10-20 3248.01,131.5 r0 top
J1 "FTSH-105-01-L-DV-K" SAMTEC_FTSH-105-01-X-DV-K 757.77,2721.48 r270 top
J2 "61301621121" FP-61301621121_HDR16-MFG 1157.37,2358.86 r270 top
J3 "61300411121" WURTH_61300411121 916.27,1706.29 r90 top
J4 "691236510002" FP-691236510002_HHR2-MFG#1 1632.85,294.94 r0 top
J5 "61300211121" WURTH_61300211121 2033.96,3419.31 r0 top
J6 "61300211121" WURTH_61300211121 2033.96,3178.08 r0 top
J7 "61300211121" WURTH_61300211121 2052.92,2169.23 r0 top
J8 "61300211121" WURTH_61300211121 2052.92,2033.94 r0 top
J9 "61300211121" WURTH_61300211121 2029.54,811.07 r0 top
J10 "61300211121" WURTH_61300211121 2029.54,675.77 r0 top
J11 "691236510002" FP-691236510002_HHR2-MFG#2 4006.14,3640.27 r90 top
J12 "691236510002" FP-691236510002_HHR2-MFG#2 4006.14,2987.7 r90 top
J13 "691236510002" FP-691236510002_HHR2-MFG#1 4006.14,2402.28 r90 top
J14 "691236510002" FP-691236510002_HHR2-MFG#1 4006.14,1670.45 r90 top
J15 "691236510002" FP-691236510002_HHR2-MFG#1 4006.14,1044.11 r90 top
J16 "691236510002" FP-691236510002_HHR2-MFG#1 4006.14,312.29 r90 top
L1 "7443320100" WE-HCC_1210 2164.41,1538.8 r0 top value=1uH
Logo1 "CAUTION HOT SURFACE" IEC_HotSurface_Small 2423.7,466.98 r0 top (schematic designator LOGO1)
Logo2 "CE Mark" CE_Mark_5mm 1680.97,1170.61 r180 bottom
Logo3 "Texas Instruments" TI_Stacked_Overlay_Small 682.39,740.67 r0 top
Logo4 "FCC disclaimer" FCC_disclaimer 88.16,851.67 r90 top
Logo5 "CAUTION HOT SURFACE" IEC_HotSurface_Small -1050.44,-87.38 r0 top (schematic designator LOGO1)
LOGO5 "WEEE logo" WEEE_Minimum 2006.39,1192.9 r180 bottom (schematic designator Logo5)
Logo6 "CAUTION.  READ USER GUIDE BEFORE USE" IEC_Caution_Small 2927.62,812.06 r180 bottom
Logo7 "CAUTION HOT SURFACE" IEC_HotSurface_Small 2322.19,1902.76 r0 top (schematic designator LOGO1)
Logo8 "CAUTION HOT SURFACE" IEC_HotSurface_Small 3114.51,3377.95 r0 top (schematic designator LOGO1)
Logo9 "CAUTION.  READ USER GUIDE BEFORE USE" IEC_Caution_Small 3151.6,2046.47 r180 bottom (schematic designator Logo6)
Logo10 "CAUTION.  READ USER GUIDE BEFORE USE" IEC_Caution_Small 2927.62,3256 r180 bottom (schematic designator Logo6)
MP1 "SJ-5303 (CLEAR)" Bumpon_SJ5003Transparent 543.34,278.35 r180 bottom
MP2 "SJ-5303 (CLEAR)" Bumpon_SJ5003Transparent 543.34,3702.71 r180 bottom
MP3 "SJ-5303 (CLEAR)" Bumpon_SJ5003Transparent 3321.79,278.35 r180 bottom
MP4 "SJ-5303 (CLEAR)" Bumpon_SJ5003Transparent 3321.79,3702.71 r180 bottom
Q1 "CSD19502Q5B" DNK0008A 1818.73,1133.97 r90 top value=80V
R1 "3352T-1-503LF" Bourns_3352T 105.09,2500.02 r90 top value=50k
R2 "3352T-1-503LF" Bourns_3352T 103.57,1996.85 r90 top value=50k
R3 "CRCW040247K0JNED" 0402 380.78,2394.13 r180 top value=47k
R4 "CRCW040247K0JNED" 0402 896.27,2381.47 r180 top value=47k
R5 "RC0603JR-071KL" 0603 904.14,2322.42 r180 top value=1.0k
R6 "RT0603BRE078KL" FP-RT0603BRE078KL_0603-MFG 906.11,2239.4 r0 top value=8k
R7 "RC0603JR-0710KL" 0603L 473.51,1220.24 r270 top value=10k
R8 "RC0603JR-0710KL" 0603L 655.49,1220.24 r270 top value=10k
R9 "RC0603JR-0710KL" 0603L 839.28,1220.24 r270 top value=10k
R10 "RC0603JR-0710KL" 0603L 473.51,1088.47 r270 top value=10k
R11 "RC0603JR-0710KL" 0603L 655.49,1088.47 r270 top value=10k
R12 "RC0603JR-0710KL" 0603L 839.28,1088.47 r270 top value=10k
R13 "RC0603FR-071KL" 0603 1591.79,3626.44 r180 top value=1.00k
R14 "RC0603JR-07330RL" 0603 1591.79,3517.21 r180 top value=330
R15 "RC0603JR-07330RL" 0603 1591.79,3407.98 r180 top value=330
R16 "RC0603JR-07330RL" 0603 1591.79,3298.75 r180 top value=330
R17 "RC0603JR-07330RL" 0603 1591.79,3189.52 r180 top value=330
R18 "RC0603JR-07330RL" 0603 1591.79,3080.28 r180 top value=330
R19 "PCS2512DR0100ET" FP-PCS2512DR0100ET_2512-MFG#1 2348.18,3537.49 r0 top
R20 "PCS2512DR0100ET" FP-PCS2512DR0100ET_2512-MFG#1 2348.18,3296.19 r0 top
R21 "PCS2512DR0100ET" FP-PCS2512DR0100ET_2512-MFG#2 3195.37,2194.06 r180 top
R22 "PCS2512DR0100ET" FP-PCS2512DR0100ET_2512-MFG#2 3064.37,1640.66 r90 top
R23 "PCS2512DR0100ET" FP-PCS2512DR0100ET_2512-MFG#2 3195.37,835.9 r180 top
R24 "PCS2512DR0100ET" FP-PCS2512DR0100ET_2512-MFG#2 3064.37,282.5 r90 top
R25 "RC0603FR-07200RL" 0603 2864.61,3829.1 r180 top value=200
R26 "RC0603FR-07200RL" 0603 2927.6,3767.28 r180 top value=200
R27 "ERJ-3GEY0R00V" 0603 2921.82,3666.46 r180 top value=0
R28 "ERJ-3GEY0R00V" 0603 2663.85,3666.39 r0 top value=0
R29 "RC0603FR-071KL" 0603 2432.34,3419.31 r0 top value=1.00k
R30 "RC0603FR-071KL" 0603 2432.34,3178.08 r0 top value=1.00k
R31 "ERJ-3GEY0R00V" 0603 2670.7,3020.43 r270 top value=0
R32 "ERJ-3GEY0R00V" 0603 2932.78,2987.82 r180 top value=0
R33 "RC0603JR-0710KL" 0603L 2183.72,2576.02 r0 top value=10k
R34 "RC0603FR-0723K2L" 0603 2242.77,2518.77 r0 top value=23.2k
R35 "RC0603JR-0710KL" 0603L 2334.45,2543.26 r270 top value=10k
R36 "ERJ-3GEY0R00V" 0603 2547.43,2413.39 r0 top value=0
R37 "ERJ-3GEY0R00V" 0603 2796.34,2443.72 r270 top value=0
R38 "RC0603FR-071KL" 0603 2451.3,2169.23 r0 top value=1.00k
R39 "RC0603FR-074K99L" 0603 2451.3,2101.58 r0 top value=4.99k
R40 "RC0603FR-071KL" 0603 2451.3,2033.94 r0 top value=1.00k
R41 "RC0603FR-074K99L" 0603 2451.3,1966.29 r0 top value=4.99k
R42 "ERJ-3GEY0R00V" 0603 2641.71,1808.68 r0 top value=0
R43 "ERJ-3GEY0R00V" 0603 2904.53,1808.8 r180 top value=0
R44 "ERJ-3GEY0R00V" 0603 2537.42,1055.22 r0 top value=0
R45 "ERJ-3GEY0R00V" 0603 2786.34,1085.56 r270 top value=0
R46 "RC0603FR-071KL" 0603 2427.92,811.07 r0 top value=1.00k
R47 "RC0603FR-074K99L" 0603 2427.92,743.42 r0 top value=4.99k
R48 "RC0603FR-071KL" 0603 2427.92,675.77 r0 top value=1.00k
R49 "RC0603FR-074K99L" 0603 2427.92,608.12 r0 top value=4.99k
R50 "ERJ-3GEY0R00V" 0603 2641.71,450.51 r0 top value=0
R51 "ERJ-3GEY0R00V" 0603 2904.53,450.64 r180 top value=0
S1 "430481025816" FP-430481025816_SMT_SW_6MM2_6MM2-MFG 855.63,3325.86 r90 top
SH1 "Jumper_2p" Harwin_D3082-05 2335.6,3891.74 r180 top
SH1-J2-1 "60900213421" Wurth_60900213421 1156.8,2615.01 r0 top
SH2 "Jumper_2p" Harwin_D3082-05 2321,227.51 r180 top
SH2-J2 "60900213421" Wurth_60900213421 1156.8,2314.53 r180 top
SH3-J2 "60900213421" Wurth_60900213421 1156.8,2214.36 r180 top
SH4-J2 "60900213421" Wurth_60900213421 1156.8,2114.2 r180 top
SH5-J2 "60900213421" Wurth_60900213421 1156.8,2514.85 r180 top
SH6-J2 "60900213421" Wurth_60900213421 1156.8,2414.69 r180 top
SH7-J2 "60900213421" Wurth_60900213421 1156.8,2714.2 r180 top
SH8-J2 "60900213421" Wurth_60900213421 1156.8,2014.2 r180 top
SH-J5 "60900213421" Wurth_60900213421 2033.96,3178.08 r0 top
SH-J6 "60900213421" Wurth_60900213421 2033.96,3419.31 r0 top
SH-J7 "60900213421" Wurth_60900213421 2052.92,2169.23 r0 top
SH-J8 "60900213421" Wurth_60900213421 2052.92,2033.94 r0 top
SH-J9 "60900213421" Wurth_60900213421 2029.54,811.07 r0 top
SH-J10 "60900213421" Wurth_60900213421 2029.54,675.77 r0 top
TP1 "5002" Keystone5002 872.65,2476.13 r180 top
TP2 "5013" Keystone5013 1427.69,2708.86 r90 top
TP3 "5012" Keystone5012 1581.99,2608.86 r90 top
TP4 "5012" Keystone5012 1431.11,2508.86 r90 top
TP5 "5012" Keystone5012 1581.99,2408.86 r90 top
TP6 "5012" Keystone5012 1431.11,2308.86 r90 top
TP7 "5012" Keystone5012 1581.99,2208.86 r90 top
TP8 "5012" Keystone5012 1431.11,2108.86 r90 top
TP9 "5011" Keystone5011 1581.39,2008.86 r90 top
TP10 "5010" Keystone5010 1280.72,288.52 r0 top
TP11 "5011" Keystone5011 1999.65,368.96 r90 top
TP12 "5002" Keystone5002 2455.02,3698.79 r270 top
TP13 "5002" Keystone5002 2562.62,3083.22 r270 top
TP14 "5002" Keystone5002 3096.94,2336.38 r90 top
TP15 "5002" Keystone5002 3057.8,1859.04 r0 top
TP16 "5010" Keystone5010 2540.59,1301.81 r90 top
TP17 "5002" Keystone5002 3096.94,978.22 r90 top
TP18 "5002" Keystone5002 3057.8,500.88 r0 top
TP19 "5012" Keystone5012 3665.37,3744.76 r90 top
TP20 "5010" Keystone5010 3665.37,3526.08 r90 top
TP21 "5012" Keystone5012 3665.37,3092.19 r90 top
TP22 "5010" Keystone5010 3665.37,2873.5 r90 top
TP23 "5012" Keystone5012 3665.37,2546.76 r90 top
TP24 "5010" Keystone5010 3665.37,2328.08 r90 top
TP25 "5012" Keystone5012 3665.37,1939.25 r90 top
TP26 "5010" Keystone5010 3665.37,1463.15 r90 top
TP27 "5012" Keystone5012 3665.37,1188.6 r90 top
TP28 "5010" Keystone5010 3665.37,929.92 r90 top
TP29 "5012" Keystone5012 3665.37,581.09 r90 top
TP30 "5010" Keystone5010 3665.37,104.98 r90 top
U1 "MSPM0G3507SRHB" RHB0032E-MFG 588.33,2351.95 r0 top
U2 "TPD4E004DRYR" DRY0006A 848.72,2993.8 r0 top
U3 "LM74700QDRQ1" D0008A-MFG#1 1500.07,1081.79 r0 top
U4 "TPSM365R3FRDNR" RDN0011A-MFG 2279.33,2711.84 r180 top
U5 "DRV81325D" D0008A-MFG#2 2799.93,3394.31 r0 top
U6 "DRV81325AQD" D0008A-MFG#1 2768.22,2067.16 r0 top
U7 "DRV81325ADDA" DDA0008B-MFG 2744.84,708.99 r0 top
U8 "INA185A2IDRLR" DRL0006A 2797.21,3743.14 r0 top
U9 "INA185A2IDRLR" DRL0006A 2797.21,3061.49 r0 top
U10 "INA185A2IDRLR" DRL0006A 2697.21,2325.68 r180 top
U11 "INA185A2IDRLR" DRL0006A 2769.12,1735 r180 top
U12 "INA185A2IDRLR" DRL0006A 2687.21,967.51 r180 top
U13 "INA185A2IDRLR" DRL0006A 2769.12,376.84 r180 top
ZZ1 "This Assembly Note is for PCB labels only" AssemblyNoteLabel -772.7,7485.29 r0 top
ZZ2 "These assemblies are ESD sensitive, ESD precautions shall be observed." AssemblyNote -767.74,7367.29 r0 top
ZZ3 "These assemblies must be clean and free from flux and all contaminants. Use of no clean flux is not acceptable." AssemblyNote -768.74,7242.29 r0 top
ZZ4 "These assemblies must comply with workmanship standards IPC-A-610 Class 2, unless otherwise specified." AssemblyNote -768.74,7097.29 r0 top

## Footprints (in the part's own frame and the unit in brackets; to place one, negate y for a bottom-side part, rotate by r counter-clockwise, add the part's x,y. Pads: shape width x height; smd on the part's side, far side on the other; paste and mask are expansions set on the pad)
0402 [mm] "0402 from SM-752 data"
  rect 0.8x0.6 smd: 1(-0.6,0) 2(0.6,0)
  silkscreen extent -1.22,-0.52 1.22,0.52, body extent -0.55,-0.3 0.55,0.3, height 0.6
0603 [mm] "0603 from SM-752 data"
  rect 1x0.95 smd: 1(-0.8,0) 2(0.8,0)
  silkscreen extent -1.52,-0.69 1.52,0.69, body extent -0.87,-0.47 0.87,0.47, height 1
0603L [mm] "0603 from SM-752 data"
  rect 0.8x0.85 smd: 1(-0.7,0) 2(0.7,0)
  silkscreen extent -0.07,-0.32 0.07,0.33, body extent -0.87,-0.47 0.87,0.47, height 1
0805_150 [mm] "0805 / 1.5 mm height"
  rect 1.15x1.45 smd: 1(-0.9,0) 2(0.9,0)
  silkscreen extent -0.1,-0.8 0.1,0.8, body extent -1.1,-0.72 1.1,0.72, height 1.5
AssemblyNote [mil] "Assembly Note"
AssemblyNoteLabel [mil] "Assembly Note for PCB Labels"
Bourns_3352T [mm] "TH, 3-Leads, Body 9.53x8.89mm, Pitch 2.54mm"
  rect 1.35x1.35 hole 0.85: 1(-2.54,0)
  round 1.35 hole 0.85: 2(0,0) 3(2.54,0)
  silkscreen extent -4.44,-2.6 4.44,7.31, body extent -4.44,-2.21 4.45,7.32, height 3.81
Bumpon_SJ5003Transparent [mil] "3M Hemispherical Bumpon transparent"
  round 1 on Mech4: 0(0,0)
  silkscreen extent -228,-228 228,228, body extent -218,-218 219,218, height 197
CE_Mark_5mm [mil] "Minimum text height for CE Mark"
  silkscreen extent -138,-98 138,98
D0008A-MFG#1 [mm] "Recommended Land Pattern"
  rrect17% 1.55x0.6 smd paste+0 mask+0: 1(-2.7,1.905) 2(-2.7,0.635) 3(-2.7,-0.635) 4(-2.7,-1.905) 5(2.7,-1.905) 6(2.7,-0.635) 7(2.7,0.635) 8(2.7,1.905)
  silkscreen extent -4.17,-2.5 1.5,2.5, body extent -3,-2.45 3,2.45, height 1.75
D0008A-MFG#2 [mm] "Recommended Land Pattern"
  rrect17% 1.55x0.6 smd: 1(-2.7,1.905) 2(-2.7,0.635) 3(-2.7,-0.635) 4(-2.7,-1.905) 5(2.7,-1.905) 6(2.7,-0.635) 7(2.7,0.635) 8(2.7,1.905)
  silkscreen extent -4.17,-2.5 1.5,2.5, body extent -3,-2.45 3,2.45, height 1.75
DDA0008B-MFG [mm] "Recommended Land Pattern"
  rrect17% 1.55x0.6 smd paste+0 mask+0: 1(-2.7,1.905) 2(-2.7,0.635) 3(-2.7,-0.635) 4(-2.7,-1.905) 5(2.7,-1.905) 6(2.7,-0.635) 7(2.7,0.635) 8(2.7,1.905)
  rrect3% 2.95x4.9 smd paste-1000 mask-1000: 9(0,0)
  silkscreen extent -4.15,-2.83 2,2.83, body extent -3.01,-2.45 3.01,2.45, height 1.7
DNK0008A [mm] "SON, 8-Leads, Body 5x6mm"
  rrect39% 0.86x0.51 smd paste+0 mask+0: 1(-2.82,1.905) 2(-2.82,0.635) 3(-2.82,-0.635) 4(-2.82,-1.905)
  rrect39% 0.86x0.51 smd paste-0.05 mask-0.05: 5(2.82,-1.905) 6(2.82,-0.635) 7(2.82,0.635) 8(2.82,1.905)
  rrect50% 0.25x0.555 on Top Paste: 9(-0.83,2.372) 9(-0.83,-2.372)
  rrect50% 0.25x0.555 on Top Solder: 9(-0.83,2.372) 9(-0.83,-2.372)
  rrect50% 0.95x1.13 on Top Paste: 9(-0.535,0) 9(-0.535,1.33) 9(-0.535,-1.33) 9(0.615,0) 9(0.615,-1.33) 9(0.615,1.33) 9(1.765,-1.33) 9(1.765,1.33) 9(1.765,0)
  rrect50% 3.58x4 on Top Solder: 9(0.75,0)
  rrect5% 4.34x5.4 smd paste+0 mask+0: 9(1.08,0)
  silkscreen extent -3.74,-2.55 -1.41,2.55, body extent -3.05,-2.55 3.05,2.55, height 1.06
DRL0006A [mm] "SOTFL, 6-Flat Leads, Body 1.2x1.6x0.6mm, Pitch 0.5mm, TI recommended"
  rrect33% 0.67x0.3 smd: 1(-0.74,0.5) 2(-0.74,0) 3(-0.74,-0.5) 4(0.74,-0.5) 5(0.74,0) 6(0.74,0.5)
  silkscreen extent -0.9,-0.95 0.5,0.95, body extent -0.8,-0.8 0.8,0.8, height 0.61
DRY0006A [mm] "PSON, 6-Leads, Body 1x1.45mm, Pitch 0.5mm, TI Recommended"
  rrect50% 0.35x0.2 smd mask+0.038: 1(-0.275,0.5)
  rrect50% 0.3x0.2 smd mask+0.038: 2(-0.3,0) 3(-0.3,-0.5) 4(0.3,-0.5) 5(0.3,0) 6(0.3,0.5)
  silkscreen extent -0.89,-0.75 0.53,0.75, body extent -0.5,-0.72 0.5,0.73, height 0.58
FCC_disclaimer [mil]
Fiducial10-20 [mm]
  round 1 smd mask+0.5: 1(0,0)
  Top Layer keep-out circle w1.178: c0,0 r0.5
FP-61301621121_HDR16-MFG [mm] "Recommended Land Pattern"
  rrect6% 1.7x1.7 hole 1.1 paste-2539.97 mask+0: 1(-8.89,-1.27)
  round 1.7 hole 1.1 paste-2539.97 mask+0: 2(-8.89,1.27) 3(-6.35,-1.27) 4(-6.35,1.27) 5(-3.81,-1.27) 6(-3.81,1.27) 7(-1.27,-1.27) 8(-1.27,1.27) 9(1.27,-1.27) 10(1.27,1.27) 11(3.81,-1.27) 12(3.81,1.27) 13(6.35,-1.27) 14(6.35,1.27) 15(8.89,-1.27) 16(8.89,1.27)
  silkscreen extent -10.31,-3.22 10.31,2.62, body extent -10.16,-2.54 10.16,2.54, height 8.89
FP-430481025816_SMT_SW_6MM2_6MM2-MFG [mm]
  rrect7% 2x1.4 smd paste+0 mask+0: 1(-3.5,2) 2(3.5,2) 3(-3.5,-2) 4(3.5,-2)
  silkscreen extent -5.17,-3.2 3.2,3.2, body extent -4.6,-3.3 4.6,3.3, height 0.25
FP-691236510002_HHR2-MFG#1 [mm]
  rrect4% 2.3x2.3 hole 1.5 paste-2539.97 mask+0: 1(-2.24,-0.175)
  round 2.3 hole 1.5 paste-2539.97 mask+0: 2(2.84,-0.175)
  silkscreen extent -5.48,-6.45 5.48,5.72, body extent -5.58,-5.82 5.58,5.82, height 0.25
FP-691236510002_HHR2-MFG#2 [mm]
  rrect4% 2.3x2.3 hole 1.5: 1(-2.24,-0.175)
  round 2.3 hole 1.5: 2(2.84,-0.175)
  silkscreen extent -5.48,-6.45 5.48,5.73, body extent -5.58,-5.82 5.58,5.82, height 0.25
FP-885012206065_0603-MFG [mm]
  rrect13% 0.8x0.8 smd paste+0 mask+0: 1(-0.75,0) 2(0.75,0)
  silkscreen extent -0.85,-0.77 0.85,0.77, body extent -1.25,-0.55 1.25,0.55, height 0.25
FP-885012206091_0603-MFG#1 [mm]
  rrect13% 0.8x0.8 smd: 1(-0.75,0) 2(0.75,0)
  silkscreen extent -0.85,-0.77 0.85,0.77, body extent -1.25,-0.55 1.25,0.55, height 0.25
FP-885012206091_0603-MFG#2 [mm]
  rrect13% 0.8x0.8 smd paste+0 mask+0: 1(-0.75,0) 2(0.75,0)
  silkscreen extent -0.85,-0.77 0.85,0.77, body extent -1.25,-0.55 1.25,0.55, height 0.25
FP-PCS2512DR0100ET_2512-MFG#1 [mm]
  rrect5% 1.9x3.68 smd: 1(-2.7,0) 2(2.7,0)
  silkscreen extent -1.38,-1.65 1.38,1.65, body extent -3.75,-1.94 3.75,1.94, height 0.25
FP-PCS2512DR0100ET_2512-MFG#2 [mm]
  rrect5% 1.9x3.68 smd paste+0 mask+0: 1(-2.7,0) 2(2.7,0)
  silkscreen extent -1.38,-1.65 1.38,1.65, body extent -3.75,-1.94 3.75,1.94, height 0.25
FP-RT0603BRE078KL_0603-MFG [mm]
  rrect13% 0.9x0.8 smd paste+0 mask+0: 1(-0.85,0) 2(0.85,0)
  silkscreen extent -0.85,-0.81 0.86,0.8, body extent -1.4,-0.55 1.4,0.55, height 0.25
FP-SMBJ36CA-13-F_SMB-MFG [mm]
  rrect4% 2.5x2.3 smd paste+0 mask+0: 1(-2.15,0) 2(2.15,0)
  silkscreen extent -2.28,-1.97 2.28,1.97, body extent -3.5,-2.07 3.5,2.07, height 0.25
Harwin_D3082-05 [mm] "Shorting Plug, 10.16mm spacing, TH"
  round 1.8 hole 1.3: 1(-5.08,0) 2(5.08,0)
  silkscreen extent -3.9,-0.53 3.9,0.53, body extent -5.6,-0.52 5.61,0.52, height 6.63
IEC_Caution_Small [mil]
  silkscreen extent -107,-93 107,92
IEC_HotSurface_Small [mil]
  silkscreen extent -107,-93 107,92
Keystone5002 [mil] "For Keystone 500x miniature loop terminals"
  round 80 hole 40: 1(0,0)
  silkscreen extent -52,-52 52,52, body extent -49,-49 49,49, height 182
Keystone5010 [mil] "Keystone Multipurpose loops"
  round 87 hole 63: 1(0,0)
  silkscreen extent -70,-70 70,70, body extent -63,-63 62,62, height 319
Keystone5011 [mil] "Keystone Multipurpose loops"
  round 87 hole 63: 1(0,0)
  silkscreen extent -70,-70 70,70, body extent -63,-63 63,62, height 319
Keystone5012 [mil] "Keystone Multipurpose loops"
  round 87 hole 63: 1(0,0)
  silkscreen extent -70,-70 70,70, body extent -63,-63 62,62, height 319
Keystone5013 [mil] "Keystone Multipurpose loops"
  round 87 hole 63: 1(0,0)
  silkscreen extent -70,-70 70,70, body extent -63,-63 62,62, height 319
RDN0011A-MFG [mm]
  rrect42% 1.2x0.475 smd paste-1000 mask-1000: 1(-1.4,1.962) 8(1.4,1.962)
  rrect57% 1.2x0.343 smd paste-1000 mask-1000: 2(-1.4,1.15) 3(-1.4,0.65) 6(1.4,0.65) 7(1.4,1.15)
  rrect13% 1.562x2.15 smd paste-1000 mask-1000: 4(-1.2,-1) 5(1.2,-1)
  rrect57% 0.292x0.9 smd paste-1000 mask-1000: 9(0.5,2.05) 11(-0.5,2.05)
  round 0.504 smd paste-1000 mask-1000: 10(0,1.005)
  Top Layer region: -0.2,2.4 -0.2,2.42 -0.185,2.457 -0.157,2.485 -0.12,2.5 -0.1,2.5 0.1,2.5 0.12,2.5 0.157,2.485 0.185,2.457 0.2,2.42 0.2,2.4 0.2,1.515 0.201,1.507 0.207,1.493 0.218,1.482 0.232,1.476 0.24,1.475 0.248,1.475 0.263,1.469 0.265,1.467 0.265,-2.032 0.237,-2.06 0.2,-2.075 0.18,-2.075 -0.18,-2.075 -0.2,-2.075 -0.237,-2.06 -0.263,-2.034 -0.263,1.469 -0.248,1.475 -0.24,1.475 -0.232,1.476 -0.218,1.482 -0.207,1.493 -0.201,1.507 -0.2,1.515
  silkscreen extent -2.68,-2.42 2.1,2.6, body extent -2.1,-2.4 2.1,2.6, height 0.25
RHB0032E-MFG [mm]
  rrect40% 0.6x0.25 smd paste+0 mask+0: 1(-2.4,1.75) 2(-2.4,1.25) 3(-2.4,0.75) 4(-2.4,0.25) 5(-2.4,-0.25) 6(-2.4,-0.75) 7(-2.4,-1.25) 8(-2.4,-1.75) 17(2.4,-1.75) 18(2.4,-1.25) 19(2.4,-0.75) 20(2.4,-0.25) 21(2.4,0.25) 22(2.4,0.75) 23(2.4,1.25) 24(2.4,1.75)
  rrect40% 0.25x0.6 smd paste+0 mask+0: 9(-1.75,-2.4) 10(-1.25,-2.4) 11(-0.75,-2.4) 12(-0.25,-2.4) 13(0.25,-2.4) 14(0.75,-2.4) 15(1.25,-2.4) 16(1.75,-2.4) 25(1.75,2.4) 26(1.25,2.4) 27(0.75,2.4) 28(0.25,2.4) 29(-0.25,2.4) 30(-0.75,2.4) 31(-1.25,2.4) 32(-1.75,2.4)
  rrect3% 3.45x3.45 smd paste-1000 mask+0: 33(0,0)
  silkscreen extent -3.37,-2.55 2.55,2.55, body extent -2.8,-2.8 2.8,2.8, height 0.25
SAMTEC_FTSH-105-01-X-DV-K [mm] "Header(Shrouded), 1.27mm, 5x2, SMT"
  rect 2.79x0.74 smd: 1(-2.035,2.54) 2(2.035,2.54) 3(-2.035,1.27) 4(2.035,1.27) 5(-2.035,0) 6(2.035,0) 7(-2.035,-1.27) 8(2.035,-1.27) 9(-2.035,-2.54) 10(2.035,-2.54)
  silkscreen extent -4.41,-3.48 3.73,3.48, body extent -2.92,-3.18 2.92,3.17, height 6.13
SMB [mil] "Molded Diode, 2-Leads, Body 5.4x3.6mm, IPC Medium Density, based on OnSemi component dimensions"
  rect 85x107.99 smd: 1(-87.01,0) 2(87.01,0)
  silkscreen extent -155,-82 125,82, body extent -106,-71 106,71, height 91
SMB-Bi [mil] "Molded Diode, 2-Leads, Body 5.4x3.6mm, IPC Medium Density, based on OnSemi component dimensions"
  rect 85x107.99 smd: 1(-87.01,0) 2(87.01,0)
  silkscreen extent -125,-79 125,79, body extent -104,-73 104,73, height 89
TI_Stacked_Overlay_Small [mil]
  silkscreen extent -418,-98 418,98
WCAP-ATUL_D10H20 [mm] "Aluminum Electrolytic Capacitors, 10x20mm"
  rrect50% 1.4x1.4 hole 0.9: 1(2.5,0)
  round 1.4 hole 0.9: 2(-2.5,0)
  silkscreen extent -5.25,-5.25 5.25,5.25, body extent -4.99,-5 5,5, height 20.31
WCAP-CSGP_0402_L1W0.5H0.5 [mm] "Ceramic Capacitors, body 1x0.5mm"
  rect 0.5x0.5 smd mask+0.038: 1(-0.5,0) 2(0.5,0)
  silkscreen extent -0.13,-0.25 0.13,0.25, body extent -0.5,-0.25 0.5,0.25, height 0.5
WCAP-CSGP_0603_L1.6W0.8H0.8_REFLOW [mm] "Ceramic Capacitors, body 1.6x0.8mm"
  rect 0.8x0.8 smd mask+0.038: 1(-0.75,0) 2(0.75,0)
  silkscreen extent -0.11,-0.39 0.12,0.41, body extent -0.8,-0.4 0.8,0.4, height 0.8
WCAP-CSGP_1206_L3.2W1.6H1.6 [mm] "Ceramic Capacitors, body 3.2x1.6mm"
  rect 0.9x1.6 smd: 1(-1.55,0) 2(1.55,0)
  silkscreen extent -0.8,-0.95 0.8,0.95, body extent -1.6,-0.8 1.6,0.8, height 1.6
WCAP-CSGP_1812_L4.5W3.2H2.5 [mm] "Ceramic Capacitors, body 4.5x3.2mm"
  rect 0.9x3.8 smd: 1(-2.2,0) 2(2.2,0)
  silkscreen extent -1.45,-1.8 1.45,1.8, body extent -2.25,-1.6 2.25,1.6, height 2.5
WE-HCC_1210 [mm] "WURTH"
  rect 2.9x5.4 smd: 1(-4.95,0) 2(4.95,0)
  silkscreen extent -6,-5.9 6,5.9, body extent -6,-5.85 6,5.85, height 10
WEEE_Minimum [mil] "WEEElie bin"
  silkscreen extent -95,-172 99,104
WL-SMCW_GREEN [mm] "WURTH"
  rect 0.8x0.8 smd: 1(-0.8,0) 2(0.8,0)
  silkscreen extent -1.9,-0.8 1.2,1.65, body extent -0.85,-0.45 0.85,0.45, height 0.8
WL-SMCW_RED [mm] "WURTH"
  rect 0.8x0.8 smd: 1(-0.8,0) 2(0.8,0)
  silkscreen extent -1.9,-0.8 1.2,1.65, body extent -0.85,-0.45 0.85,0.45, height 0.8
Wurth_60900213421 [mil] "Shunt, 2.54mm, Black"
  round 1 on Mech3: 0(0,0)
  body extent -98,-48 98,48, height 338
WURTH_61300211121 [mm] "Header, 2.54mm, 2x1, TH"
  rrect50% 1.65x1.65 hole 1.15: 1(-1.27,0)
  round 1.65 hole 1.15: 2(1.27,0)
  silkscreen extent -2.54,-1.27 2.54,2.03, body extent -2.54,-1.27 2.54,1.27, height 8.54
WURTH_61300411121 [mm] "Header, 2.54mm, 4x1, TH"
  rrect50% 1.65x1.65 hole 1.15: 1(-3.81,0)
  round 1.65 hole 1.15: 2(-1.27,0) 3(1.27,0) 4(3.81,0)
  silkscreen extent -5.08,-1.27 5.08,1.9, body extent -5.08,-1.27 5.08,1.27, height 8.54

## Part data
C1: library part CMP-0119398-1, "WCAP-CSGP Multilayer Ceramic Chip Capacitor, General Purpose, size 0603, X7R, 22nF, 50VDC", Capacitance Tolerance=+/-10%, Case/Size Code=0603, Insulation Resistance=10GOhm, Manufacturer="Wurth Elektronik", Operating Temperature Max=125°C, Operating Temperature Min=-55°C, Rated Voltage (DC)=50V
C2 C17 C18: library part CMP-0119739-1, "WCAP-CSGP Multilayer Ceramic Chip Capacitor, General Purpose, size 1812, X7R, 2.2µF, 50VDC", Capacitance Tolerance=+/-10%, Case/Size Code=1812, Insulation Resistance=0.2GOhm, Manufacturer="Wurth Elektronik", Operating Temperature Max=125°C, Operating Temperature Min=-55°C, Rated Voltage (DC)=50V
C3 C8 C15 C20: library part CMP-0119636-1, "WCAP-CSGP Multilayer Ceramic Chip Capacitor, General Purpose, size 1206, X7R, 1µF, 50VDC", Capacitance Tolerance=+/-10%, Case/Size Code=1206, Insulation Resistance=0.5GOhm, Manufacturer="Wurth Elektronik", Operating Temperature Max=125°C, Operating Temperature Min=-55°C, Rated Voltage (DC)=50V
C4: library part CMP-0860569-1, "CAP, CERM, 10 µF, 25 V,+/- 10%, X5R, 0603", Cap_Case=0603, Manufacturer=MuRata, TempCo=X5R, Tolerance_%=10%, Value2=25V, ValueDisplayed=10µF
C5: library part CMP-0006837-4, "CAP, CERM, 0.1 uF, 50 V, +/- 10%, X7R, 0603", Cap_Case=0603, Manufacturer="Wurth Elektronik", TempCo=X7R, Tolerance_%=10%, Value1=Unknown, Value2=50V, ValueDisplayed=0.1uF
C6: library part CMP-0119380-1, "WCAP-CSGP Multilayer Ceramic Chip Capacitor, General Purpose, size 0603, X7R Class II, 470nF, 25VDC", Capacitance Tolerance=+/-10%, Case/Size Code=0603, Insulation Resistance=1.1GOhm, Manufacturer="Wurth Elektronik", Operating Temperature Max=125°C, Operating Temperature Min=-55°C, Rated Voltage (DC)=25V
C7: library part CMP-0102582-1, "WCAP-ATUL Aluminum Electrolytic Capacitor, Radial, THT, D10 x H20mm, 82µF, 100V", Capacitance Tolerance=20%, Leakage Current=82uA, Manufacturer="Wurth Elektronik", Operating Temperature Max=105°C, Operating Temperature Min=-40°C, Rated Voltage (DC)=100V, Ripple Current=600mA
C9 C14 C19: library part CMP-0119402-1, "WCAP-CSGP Multilayer Ceramic Chip Capacitor, General Purpose, size 0603, X7R, 100nF, 50VDC", Capacitance Tolerance=+/-10%, Case/Size Code=0603, Insulation Resistance=5GOhm, Manufacturer="Wurth Elektronik", Operating Temperature Max=125°C, Operating Temperature Min=-55°C, Rated Voltage (DC)=50V
C10 C13: library part CMP-0119297-1, "WCAP-CSGP Multilayer Ceramic Chip Capacitor, General Purpose, size 0402, X7R, 10nF, 50VDC", Capacitance Tolerance=+/-10%, Case/Size Code=0402, Insulation Resistance=10GOhm, Manufacturer="Wurth Elektronik", Operating Temperature Max=125°C, Operating Temperature Min=-55°C, Rated Voltage (DC)=50V
C11 C12: library part CMP-0119291-1, "WCAP-CSGP Multilayer Ceramic Chip Capacitor, General Purpose, size 0402, X7R, 1nF, 50VDC", Capacitance Tolerance=+/-10%, Case/Size Code=0402, Insulation Resistance=10GOhm, Manufacturer="Wurth Elektronik", Operating Temperature Max=125°C, Operating Temperature Min=-55°C, Rated Voltage (DC)=50V
C16: library part CMP-0120893-1, "10000 pF ±10% 25V Ceramic Capacitor X7R 0603 (1608 Metric)", Digikey Part Number=732-7983-1-ND, Manufacturer="Wurth Electronics", Mouser Part Number=710-885012206065, Operating Temperature Range="-55°C to +125°C", TempCo=15%, Temperature Characteristic=X7R, Tolerance_%=10%, ValueDisplayed=10nF
C21: library part CMP-0050226-1, "WCAP-CSGP Multilayer Ceramic Chip Capacitor, General Purpose, size 0402, NP0, 47pF, 16VDC", Capacitance Tolerance=+/-5%, Case/Size Code=0402, Insulation Resistance=10GOhm, Manufacturer="Wurth Elektronik", Operating Temperature Max=125°C, Operating Temperature Min=-55°C, Rated Voltage (DC)=16V
C22 C23: library part CMP-0078154-1, "CAP, CERM, 10 µF, 16 V,+/- 20%, X5R, 0805", Cap_Case=0805, Manufacturer="Wurth Elektronik", Supplier Part Number 1=732-7624-1-ND, TempCo=X5R, Tolerance_%=20%, Value2=16V, ValueDisplayed=10µF
C24 C27 C30 C33 C36 C39: library part CMP-0006219-2, "CAP, CERM, 0.1 uF, 6.3 V, +/- 20%, X5R, 0402", Cap_Case=0402, Manufacturer="Wurth Elektronik", Supplier Part Number 1=732-7478-1-ND, TempCo=X5R, Tolerance_%=20%, Value1=Unknown, Value2=6.3V, ValueDisplayed=0.1uF
C25 C28 C31 C34 C37 C40: library part CMP-0006829-4, "CAP, CERM, 0.1 uF, 16 V, +/- 10%, X7R, 0603", Cap_Case=0603, Manufacturer="Wurth Elektronik", Supplier Part Number 1=710-885012206046, TempCo=X7R, Tolerance_%=10%, Value1=Unknown, Value2=16V, ValueDisplayed=0.1uF
C26 C29 C32 C35 C38 C41: library part CMP-0120895-1, "0.022 µF ±10% 50V Ceramic Capacitor X7R 0603 (1608 Metric)", Digikey Part Number=732-8009-1-ND, Manufacturer="Wurth Electronics", Mouser Part Number=710-885012206091, Operating Temperature Range="-55°C to +125°C", TempCo=15%, Temperature Characteristic=X7R, Tolerance_%=10%, ValueDisplayed=22nF
D1 D2: library part CMP-0002894-2, "LED, Green, SMD", Color=green, Manufacturer="Wurth Elektronik", Value1=W, Value2=2V
D3 D4 D5 D6: library part CMP-0002947-3, "LED, Red, SMD", Color=Red, Manufacturer="Wurth Elektronik", Power_TotalModule=72mW, Value1=0.072W, Value2=2V
D7: library part CMP-0098087-1, "58.1V Clamp 10.3A Ipp Tvs Diode Surface Mount SMB", Breakdown Voltage=40V, Clamping Voltage=58.1V, Digikey Part Number=SMBJ36CA-FDICT-ND, Manufacturer="Diodes Inc", Mouser Part Number=621-SMBJ36CA-13-F, Operating Temperature Range="-55°C to +150°C"
D8 D9 D10 D11 D12 D13: library part CMP-0005564-3, "Diode, TVS, Bi, 33 V, SMB", Manufacturer="Diodes Inc.", Value1=600W
D14 D15 D16 D17 D18 D19: library part CMP-0028778-2, "Diode, Schottky, 40 V, 2 A, AEC-Q101, SMB", Manufacturer="ON Semiconductor", Value1=2A, Value2=0.5V
FID1 FID2 FID3: library part CMP-0077181-1, "Fiducial mark.  There is nothing to buy or mount.", Manufacturer=N/A
J1: library part CMP-0075634-2, "Header(Shrouded), 1.27mm, 5x2, Gold, SMT", Color=Black, Current_A=3.3A, Manufacturer=Samtec, Supplier Part Number 1=SAM8799-ND
J2: library part CMP-0125672-1, "Connector Header Through Hole 16 position 0.100\" (2.54mm)", Current_A=3A, Digikey Part Number=732-5299-ND, Manufacturer=Wurth, Mouser Part Number=710-61301621121, Operating Temperature Range="-40°C to +105°C", Voltage_V=250V
J3: library part CMP-0054798-2, "Header, 2.54 mm, 4x1, Gold, TH", Color=Black, Manufacturer="Wurth Elektronik", Supplier Part Number 1=732-5317-ND
J4 J11 J12 J13 J14 J15 J16: library part CMP-0121282-1, "2 Position Wire to Board Terminal Block Horizontal with Board 0.200\" (5.08mm) Through Hole", Current_A=20A, Digikey Part Number=732-10995-ND, Manufacturer="Wurth Electronics", Mouser Part Number=710-691236510002, Operating Temperature Range="-30°C to +120°C", Voltage_V=300V
J5 J6 J7 J8 J9 J10: library part CMP-0054794-2, "Header, 2.54 mm, 2x1, Gold, TH", Color=Black, Manufacturer="Wurth Elektronik", Supplier Part Number 1=732-5315-ND
L1: library part CMP-0063986-1, "Inductor, Shielded Drum Core, Ferrite, 1 uH, 24 A, 0.0012 ohm, SMD", Manufacturer="Wurth Elektronik", Supplier Part Number 1=732-2138-1-ND, Value1="0.0012 ohm", Value2=24A, ValueDisplayed=1uH
Logo1 Logo5 Logo7 Logo8: library part CMP-0074837-2, "IEC 61010-1 Hot Surface Warning", Manufacturer="Texas Instruments"
Logo2: library part CMP-0074844-2, Manufacturer="Texas Instruments"
Logo3: library part CMP-0074838-1, "Texas Instrument Corporate Signature"
Logo4: library part CMP-0074847-1, "FCC_disclaimer"
LOGO5: library part CMP-0074769-4, Manufacturer="Texas Instruments"
Logo6 Logo9 Logo10: library part CMP-0074836-1, "IEC 61010-1 Caution Warning"
MP1 MP2 MP3 MP4: library part CMP-0003620-1, "Bumpon, Hemisphere, 0.44 X 0.20, Clear", Manufacturer=3M, Supplier Part Number 1=SJ5303-7-ND
Q1: library part CMP-0000915-2, "MOSFET, N-CH, 80 V, 100 A, DNK0008A (VSON-CLIP-8)", Alternate Manufacturer=None, Manufacturer="Texas Instruments", Supplier Part Number 1=296-37194-1-ND, Value2="48 nC"
R1 R2: library part CMP-0001777-2, "Trimming Potentiometer, 50K, 0.5W, TH", Manufacturer=Bourns, Supplier Part Number 1=3352T-503LF-ND
R3 R4: library part CMP-0026935-3, "RES, 47 k, 5%, 0.063 W, AEC-Q200 Grade 0, 0402", Manufacturer=Vishay-Dale, Power_W=63mW, Supplier Part Number 1=541-47KJCT-ND, TempCo="200 ppm/C", Tolerance_%=5%, Value2=0.063W, Value_Code=47k0, ValueDisplayed=47k
R5: library part CMP-0025899-5, "RES, 1.0 k, 5%, 0.1 W, 0603", Manufacturer=Yageo, Power_W=100mW, Supplier Part Number 1=311-1.0KGRCT-ND, TempCo="100 ppm/C", Tolerance_%=5%, Value2=0.1W, Value_Code=1k00, ValueDisplayed=1.0k
R6: library part CMP-0122747-1, "8 kOhms ±0.1% 0.1W, 1/10W Chip Resistor 0603 (1608 Metric) Thin Film", Digikey Part Number=13-RT0603BRE078KLCT-ND, Manufacturer=Yageo, Mouser Part Number=603-RT0603BRE078KL, Operating Temperature Range="-55°C to +155°C", Power_W=100mW, TempCo=50ppm/°C, Tolerance_%=0.1%
R7 R8 R9 R10 R11 R12 R33: library part CMP-0025886-5, "RES, 10 k, 5%, 0.1 W, 0603", Manufacturer=Yageo, Power_W=100mW, Supplier Part Number 1=311-10KGRCT-ND, TempCo="100 ppm/C", Tolerance_%=5%, Value2=0.1W, Value_Code=10k0, ValueDisplayed=10k
R13 R29 R30 R38 R40 R46 R48: library part CMP-0022895-5, "RES, 1.00 k, 1%, 0.1 W, 0603", Manufacturer=Yageo, Power_W=100mW, Supplier Part Number 1=311-1.00KHRCT-ND, TempCo="100 ppm/C", Tolerance_%=1%, Value2=0.1W, Value_Code=1k00, ValueDisplayed=1.00k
